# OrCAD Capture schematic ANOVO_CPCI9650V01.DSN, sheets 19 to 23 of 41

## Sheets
19 -GIGA LAN1: size C; title: 19--GIGA LAN1
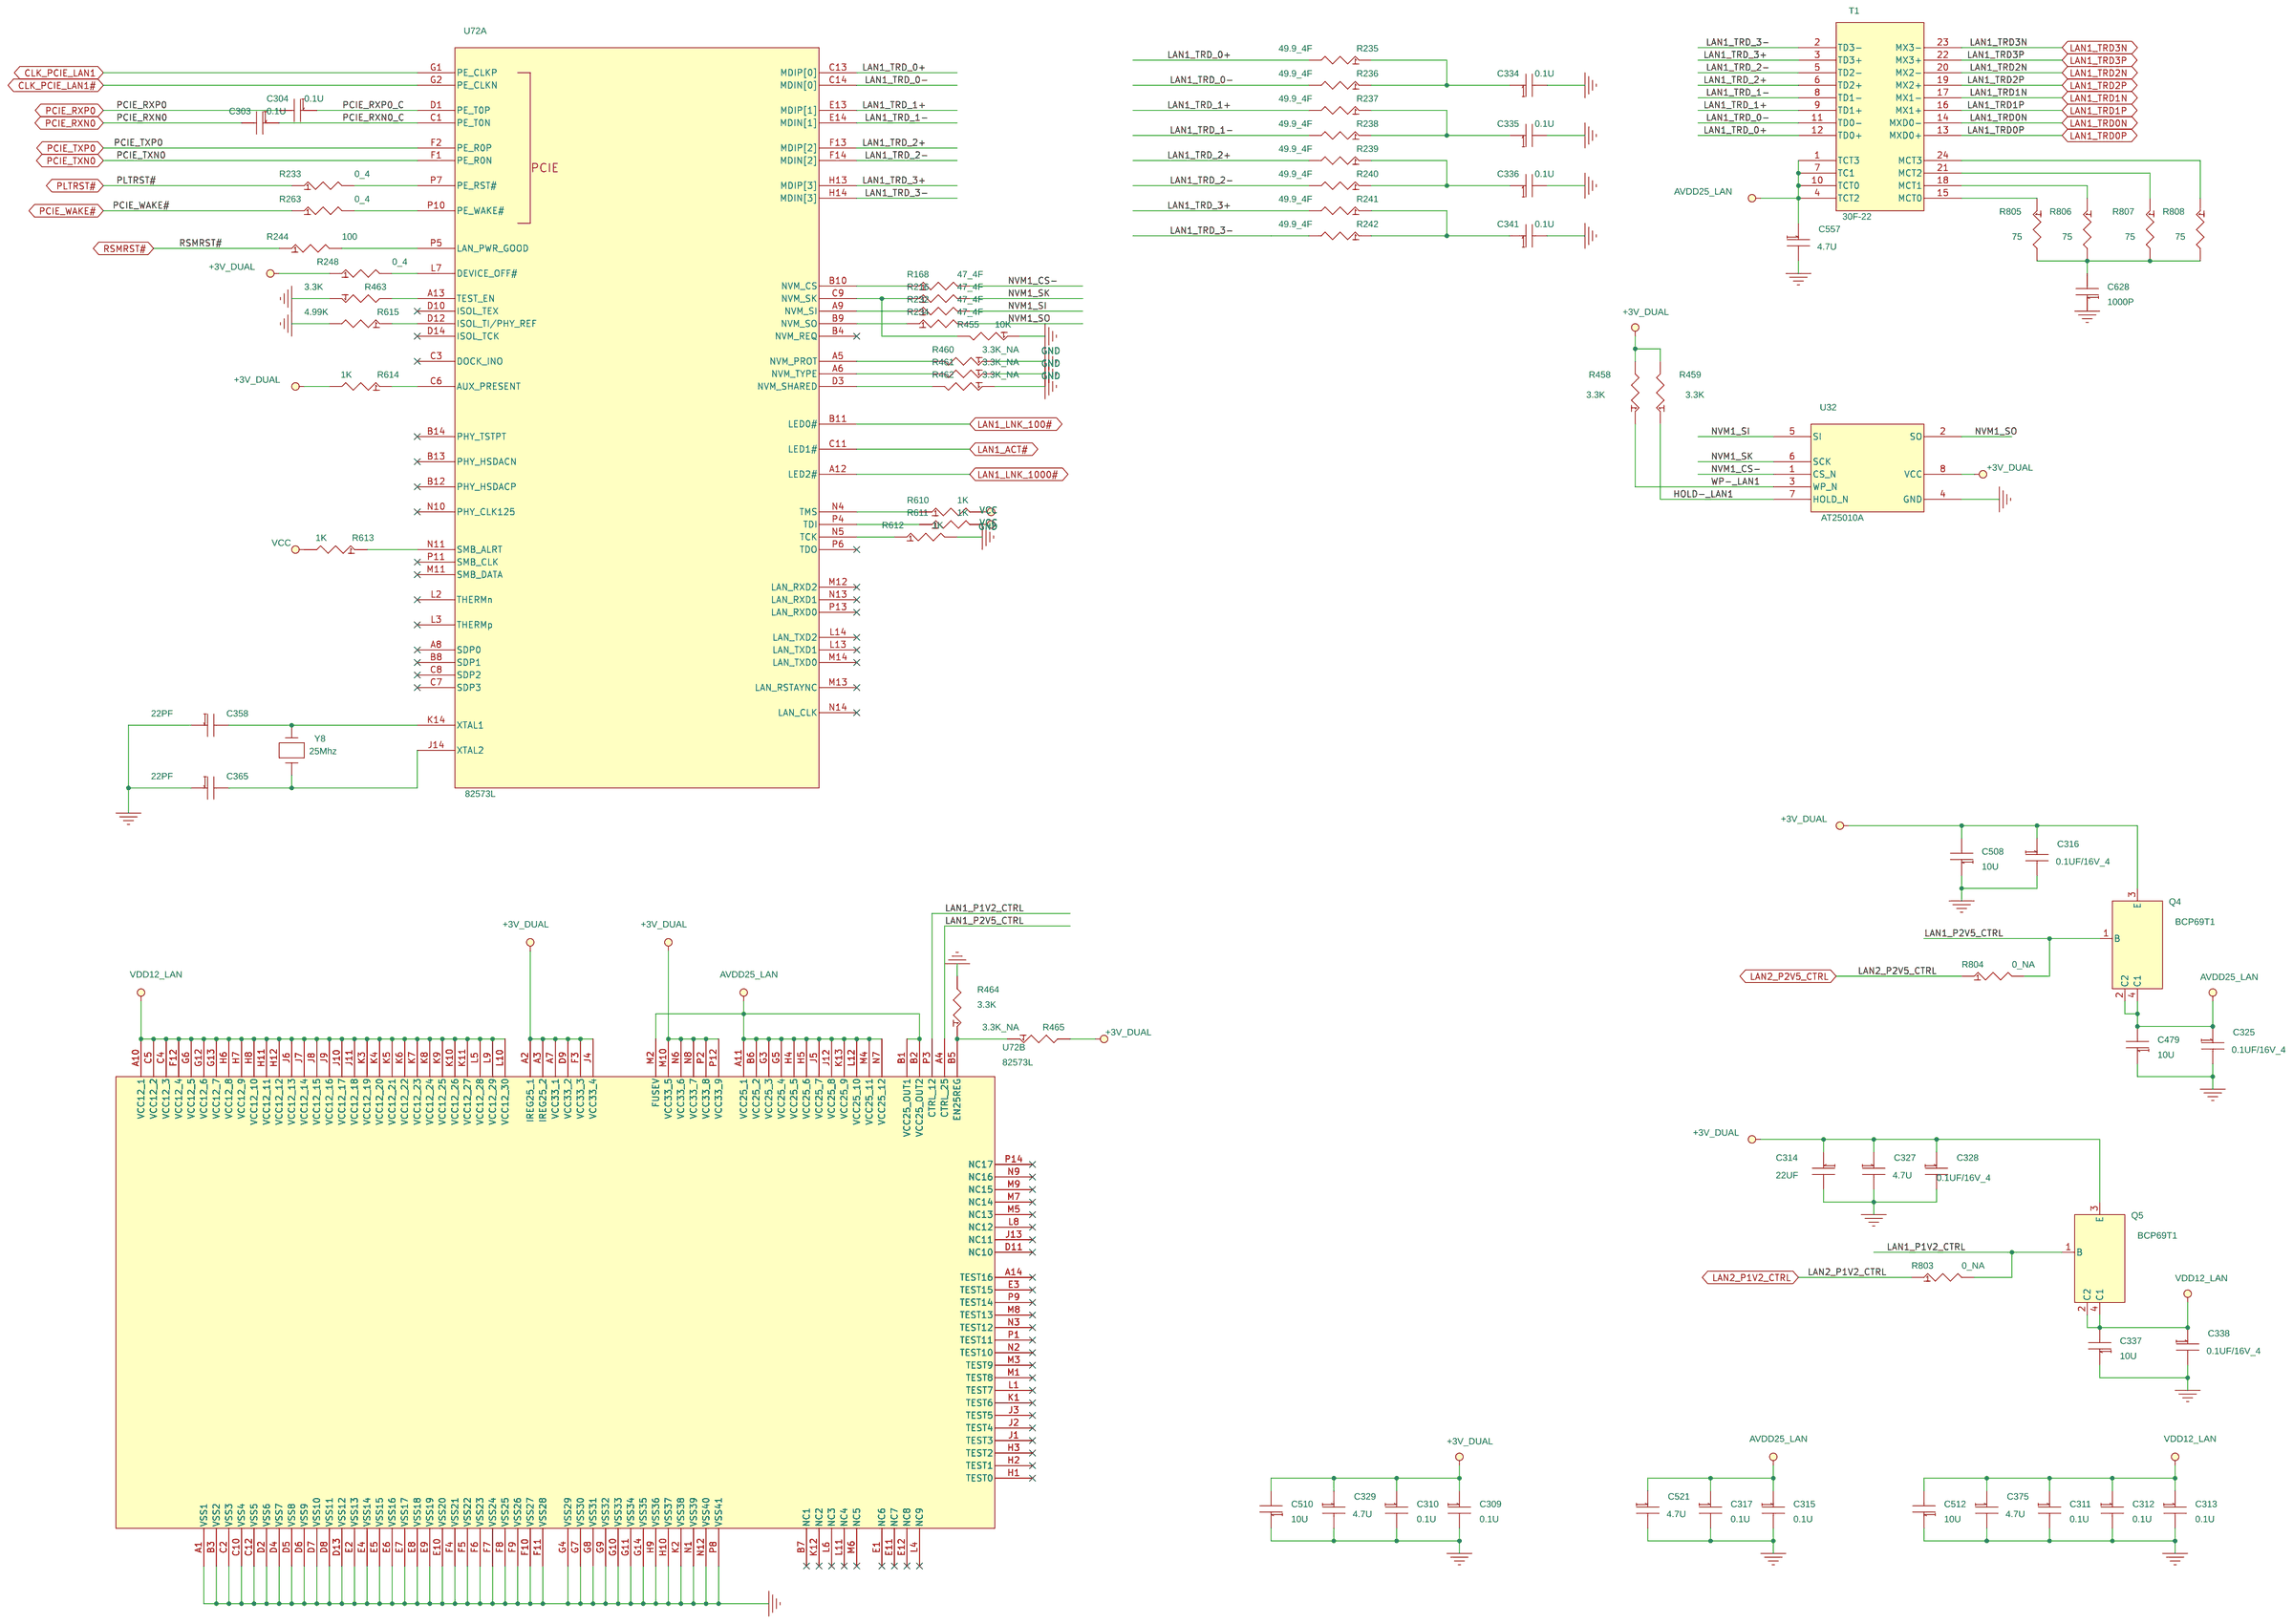
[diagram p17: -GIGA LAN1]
20 -GIGA LAN2: size C; title: 20--GIGA LAN2
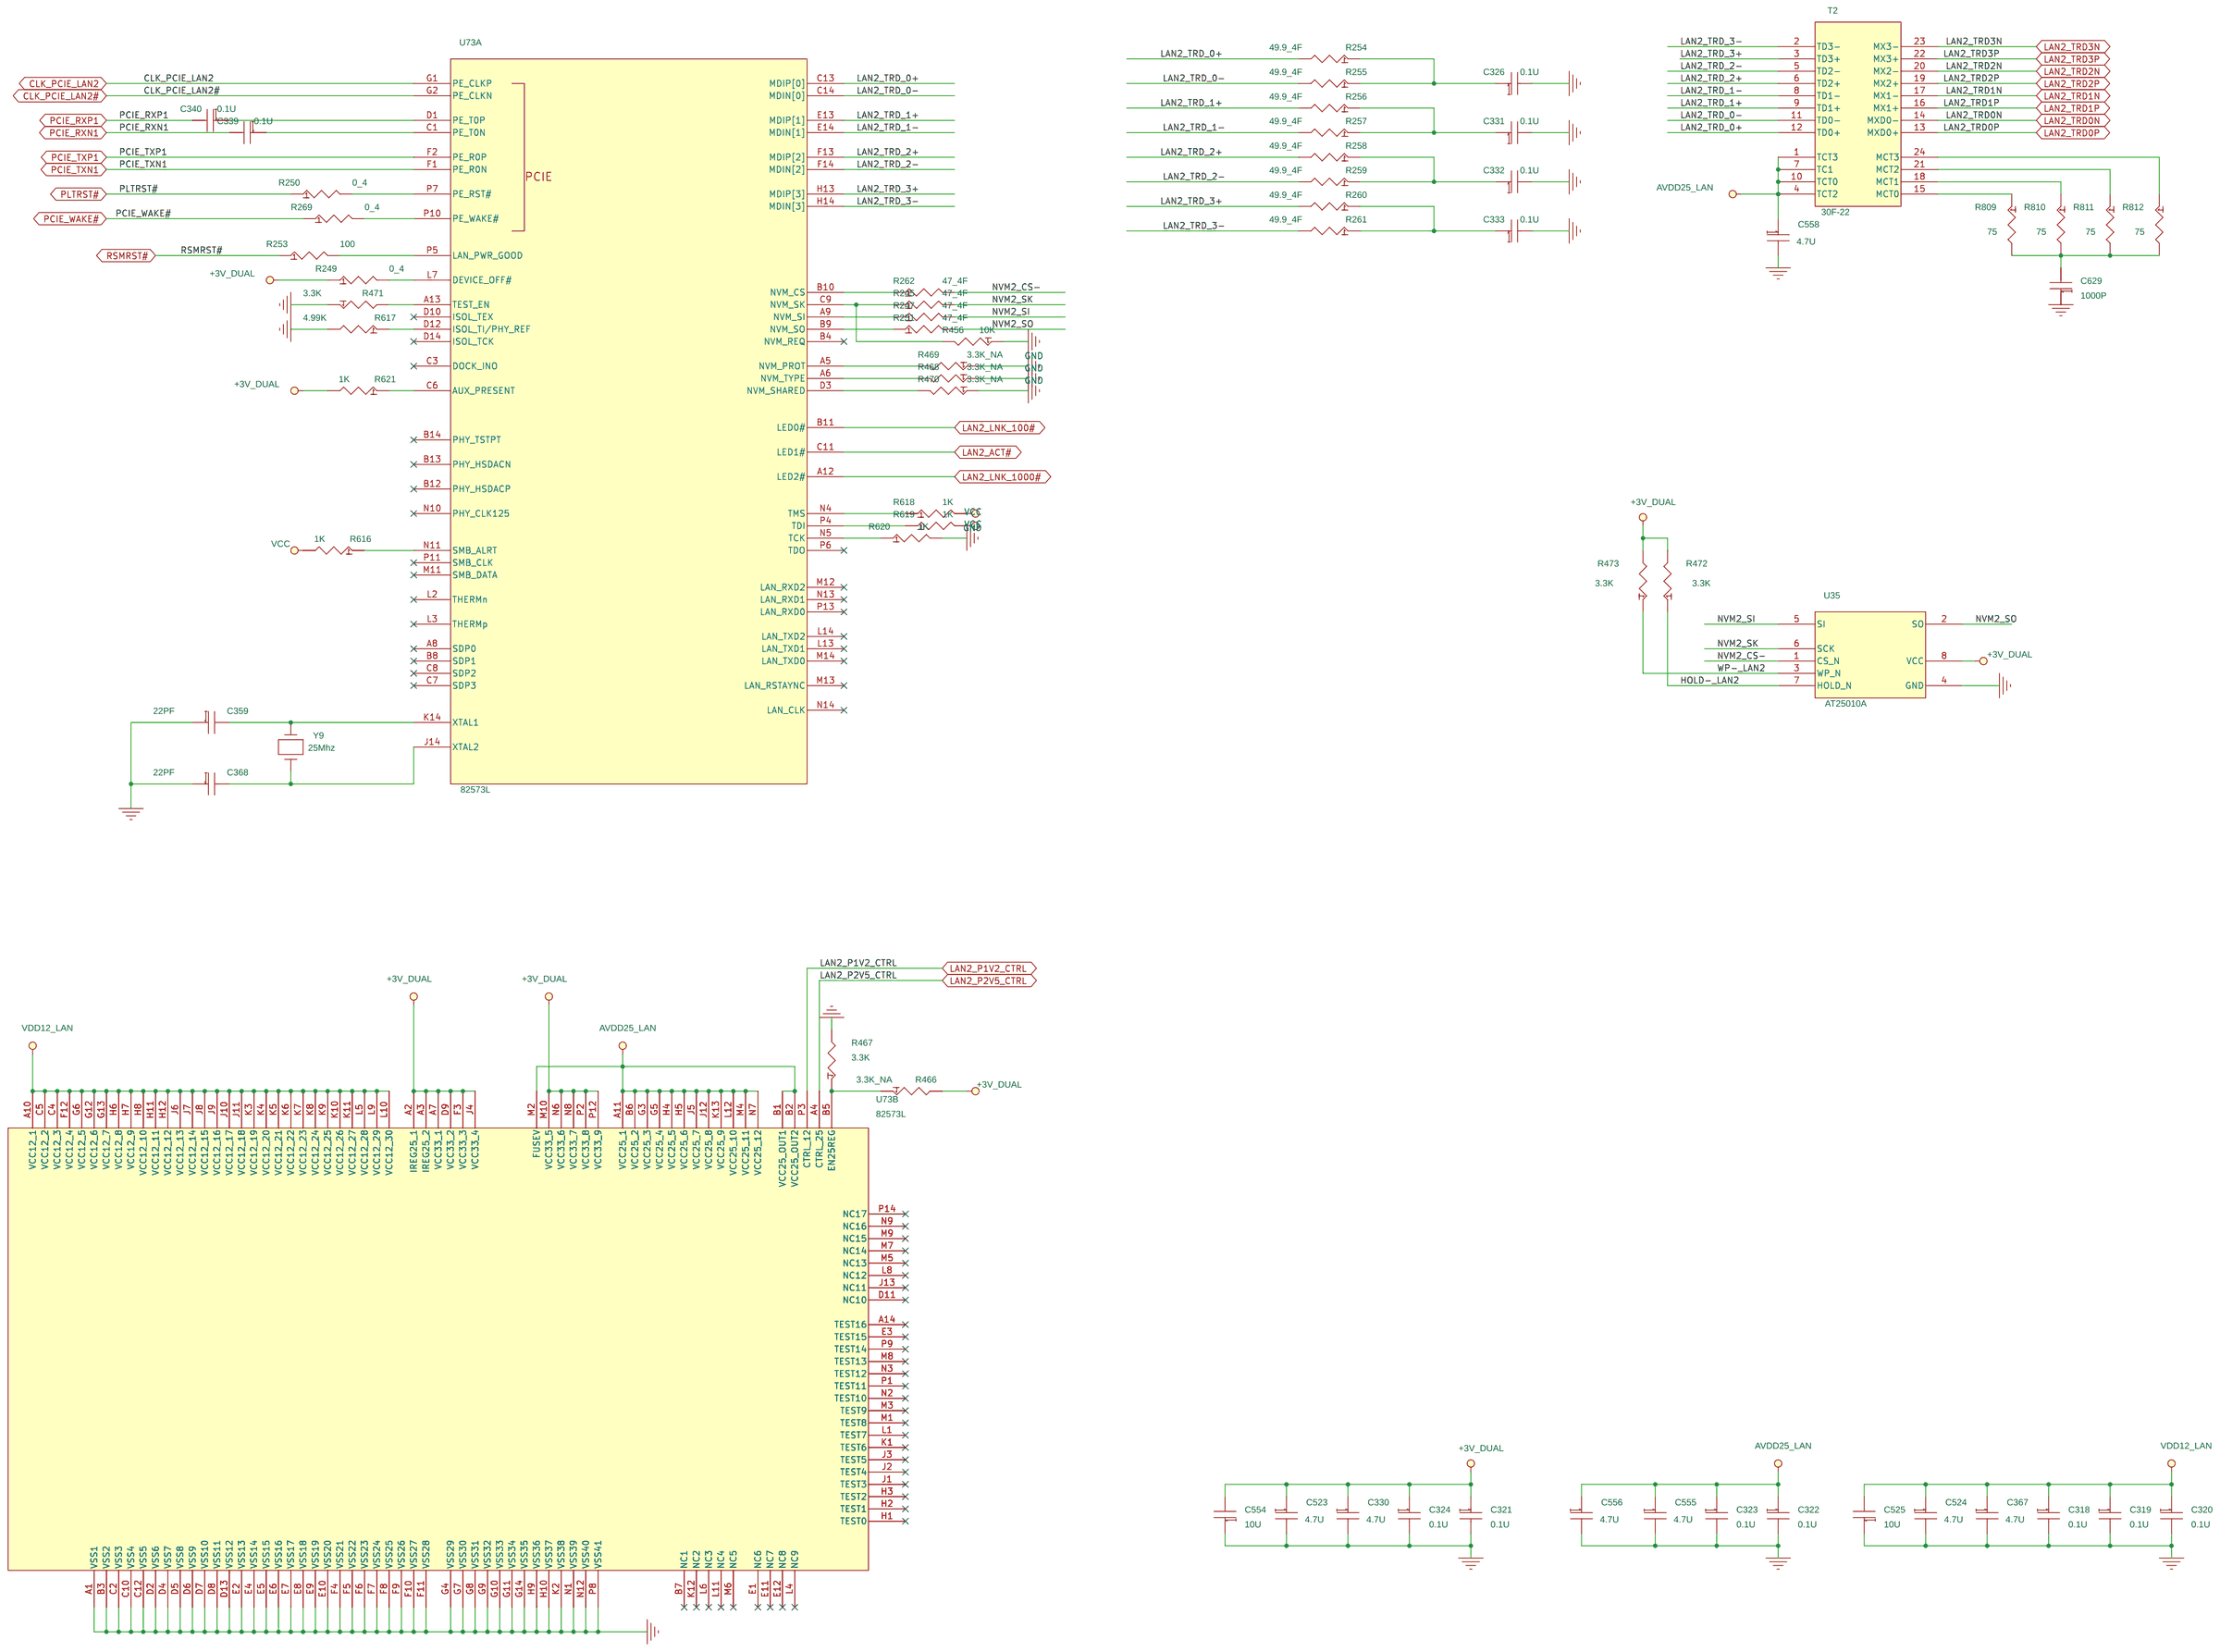
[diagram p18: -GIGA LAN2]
21 -SIO ITE8781F 4 COM PORTS: size C; title: 21--82559 PCI LAN
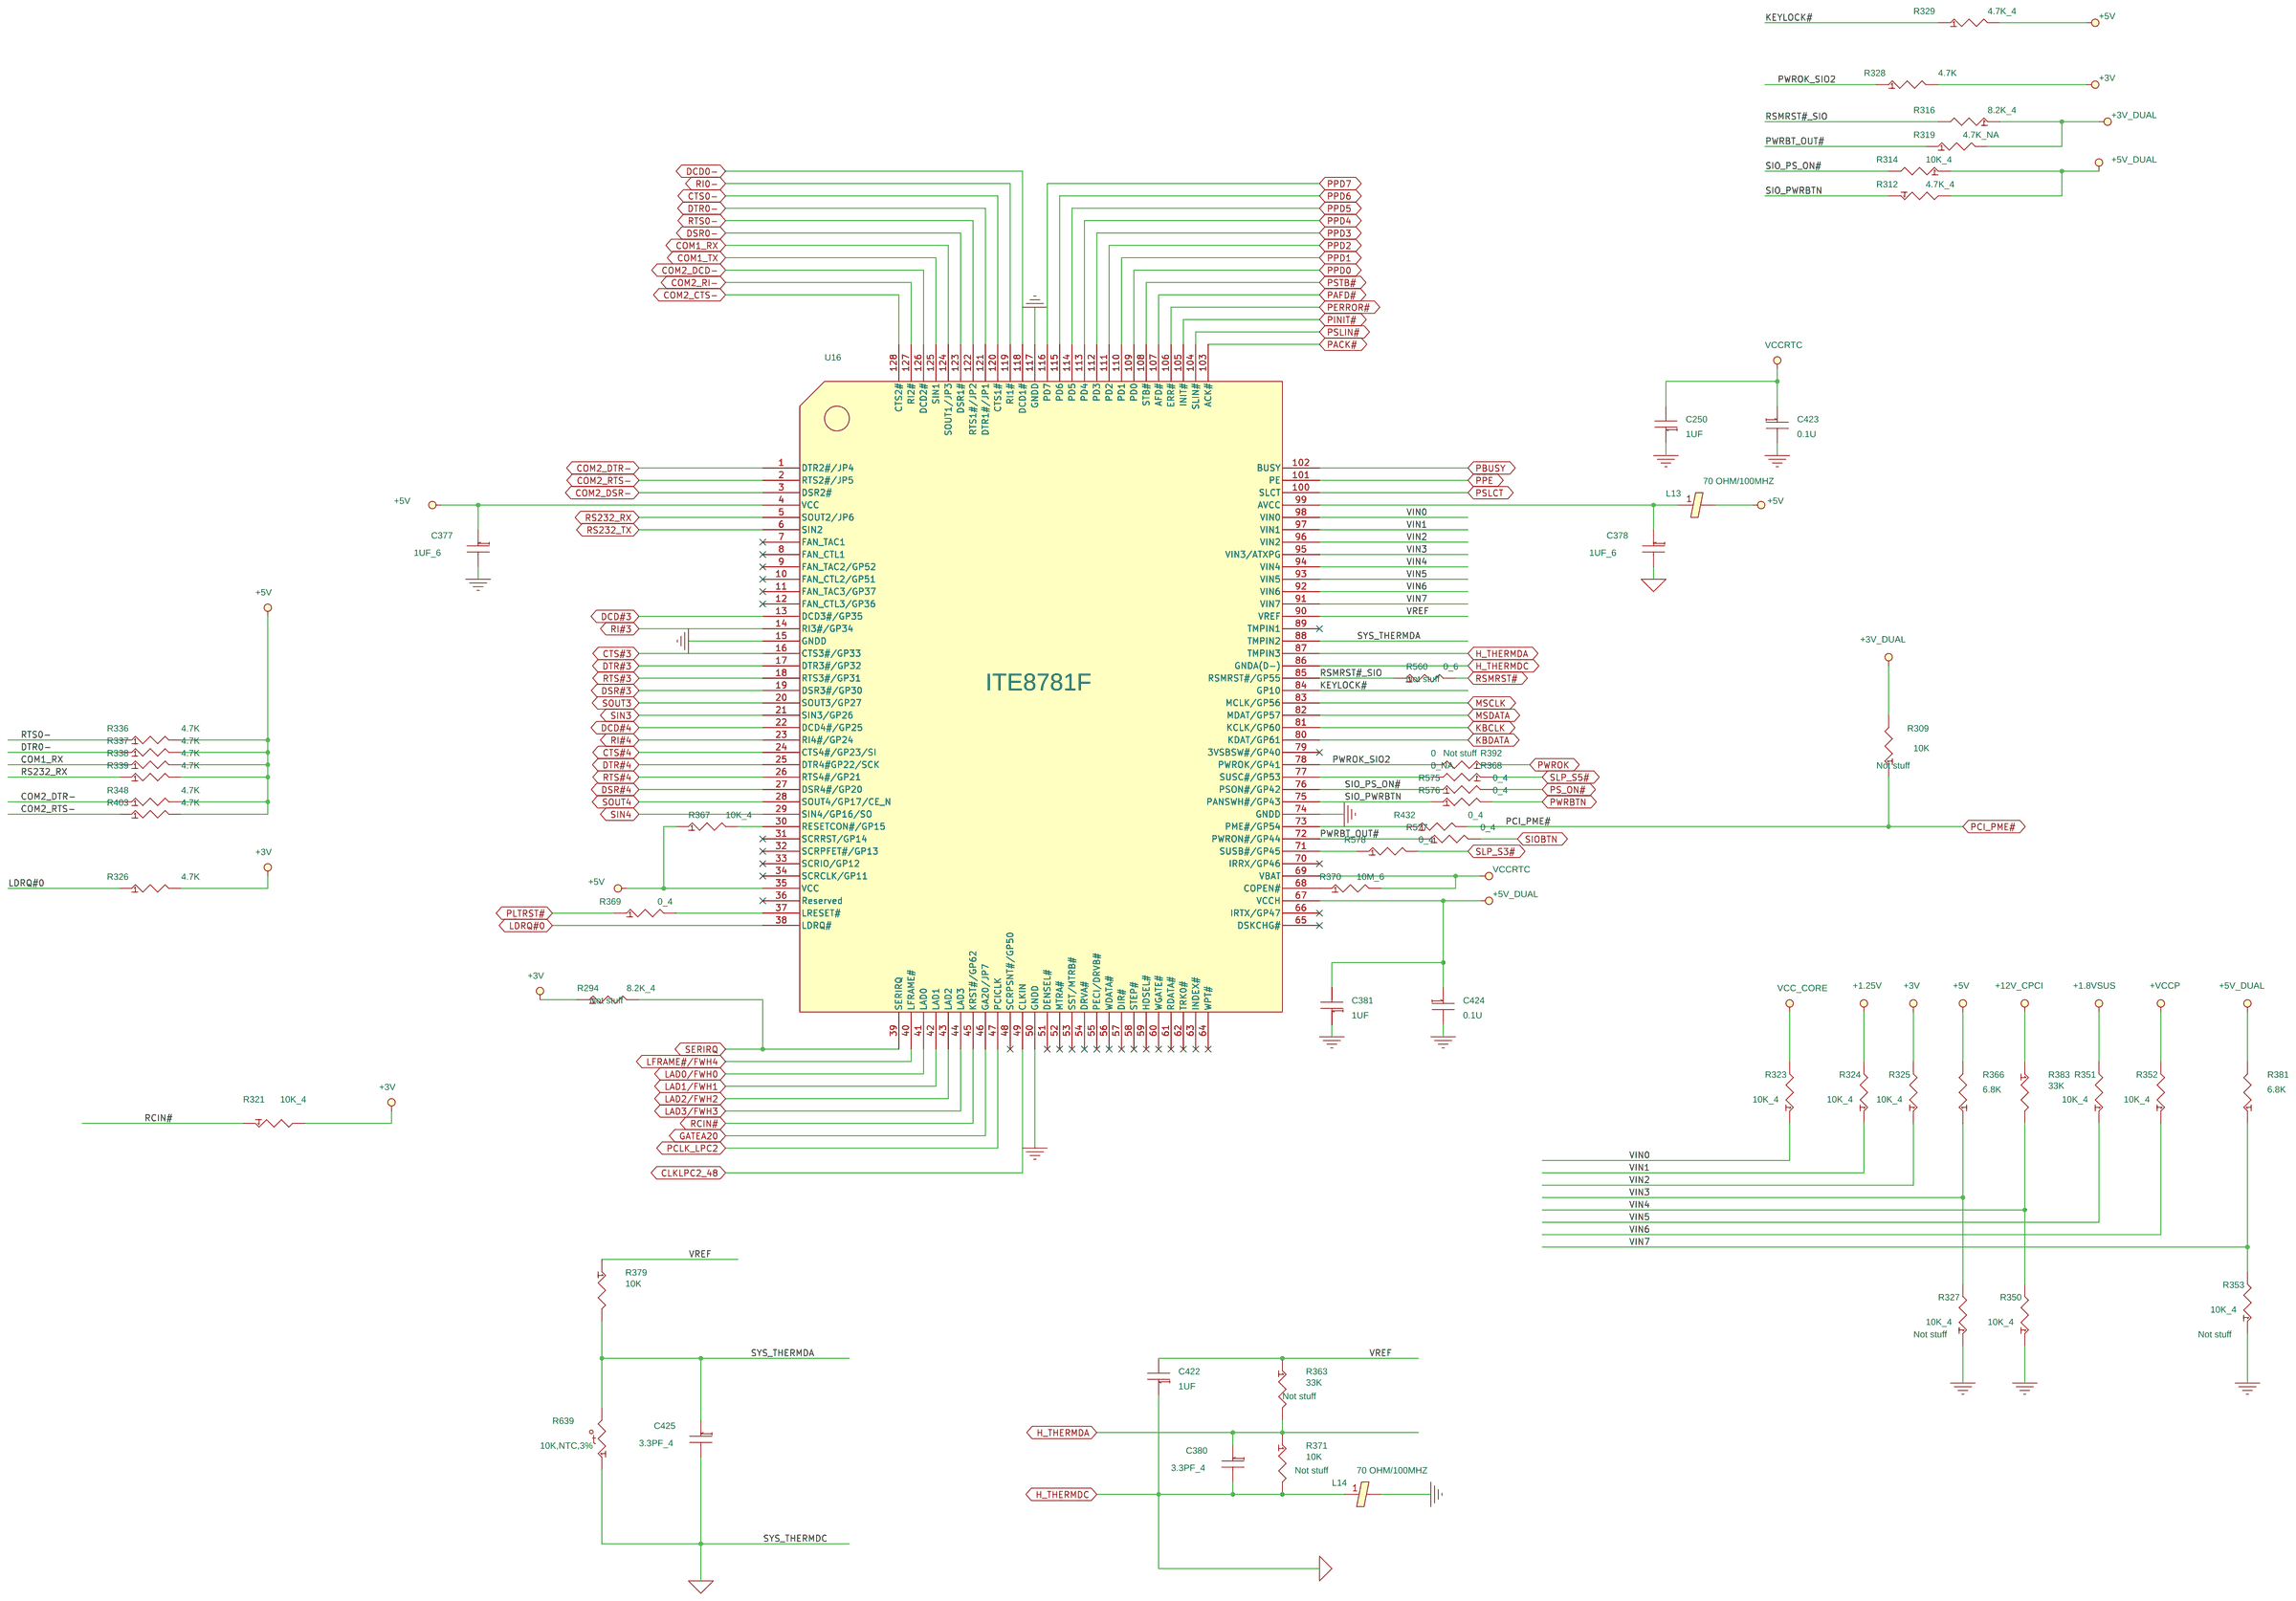
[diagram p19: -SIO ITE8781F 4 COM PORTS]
22 -COM 3 4 RS232: size C; title: 22--NC
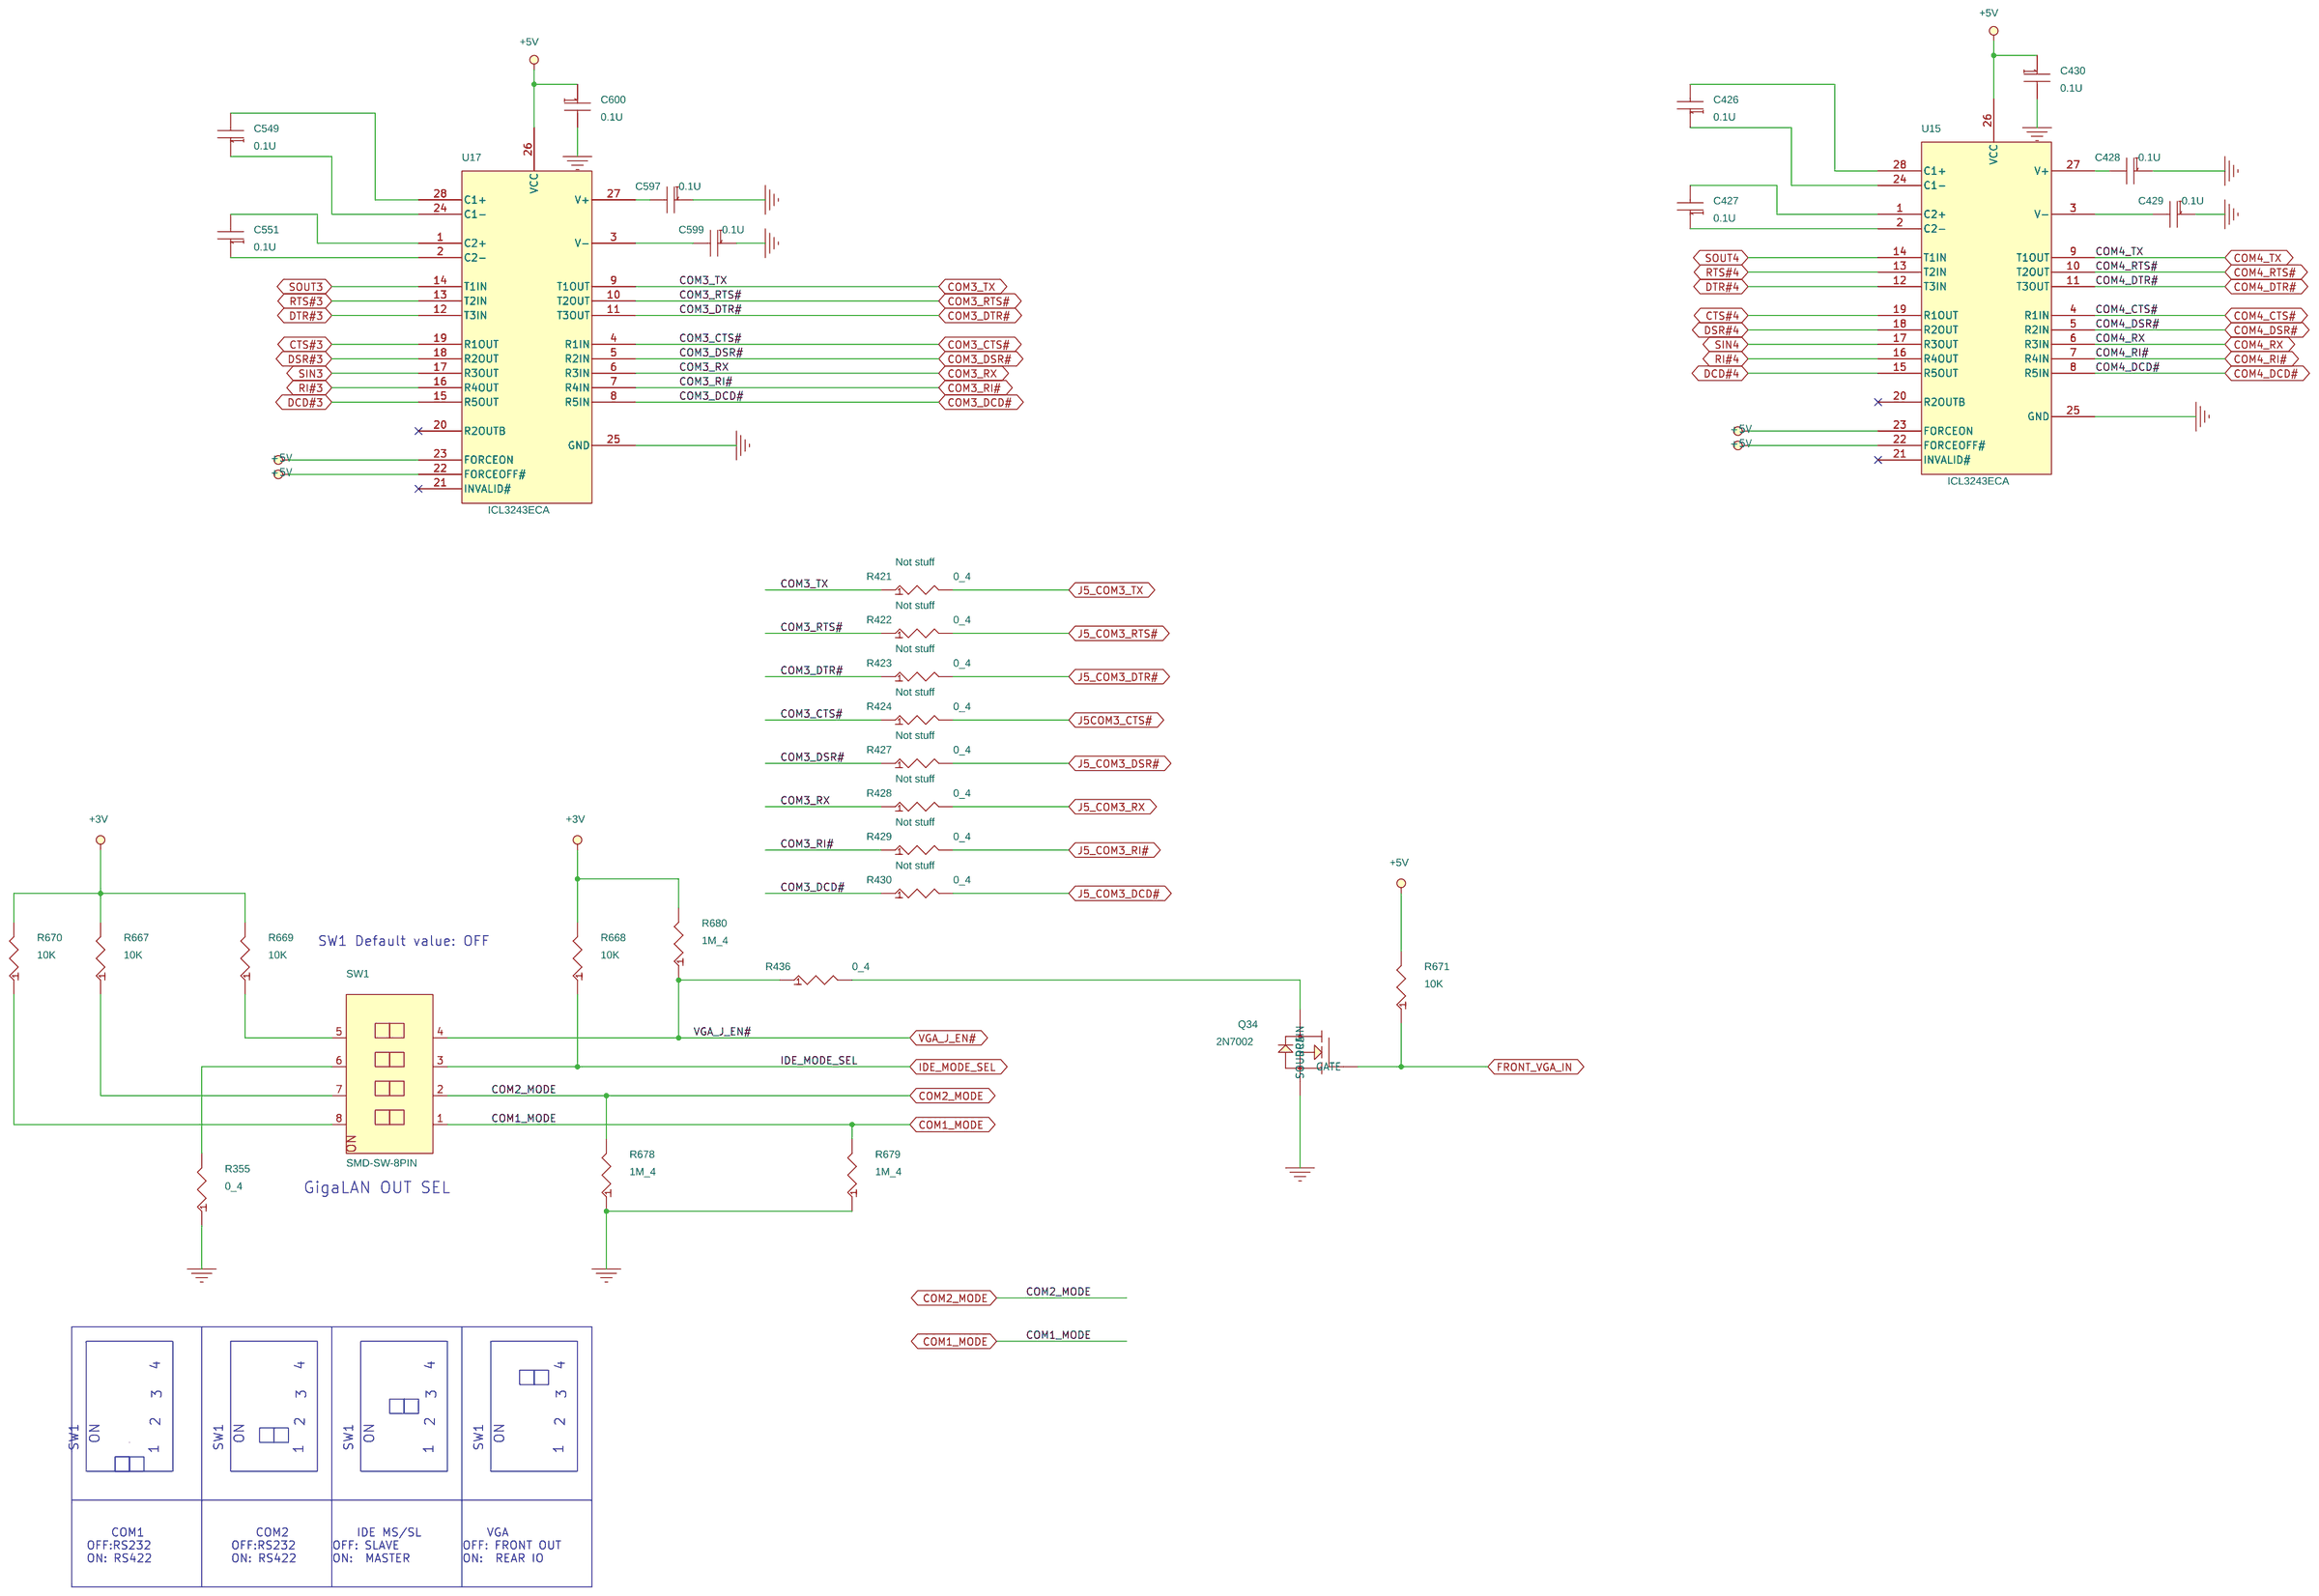
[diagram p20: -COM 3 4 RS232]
23 -CODAC ALC888: size C; title: 23--CODAC ALC888
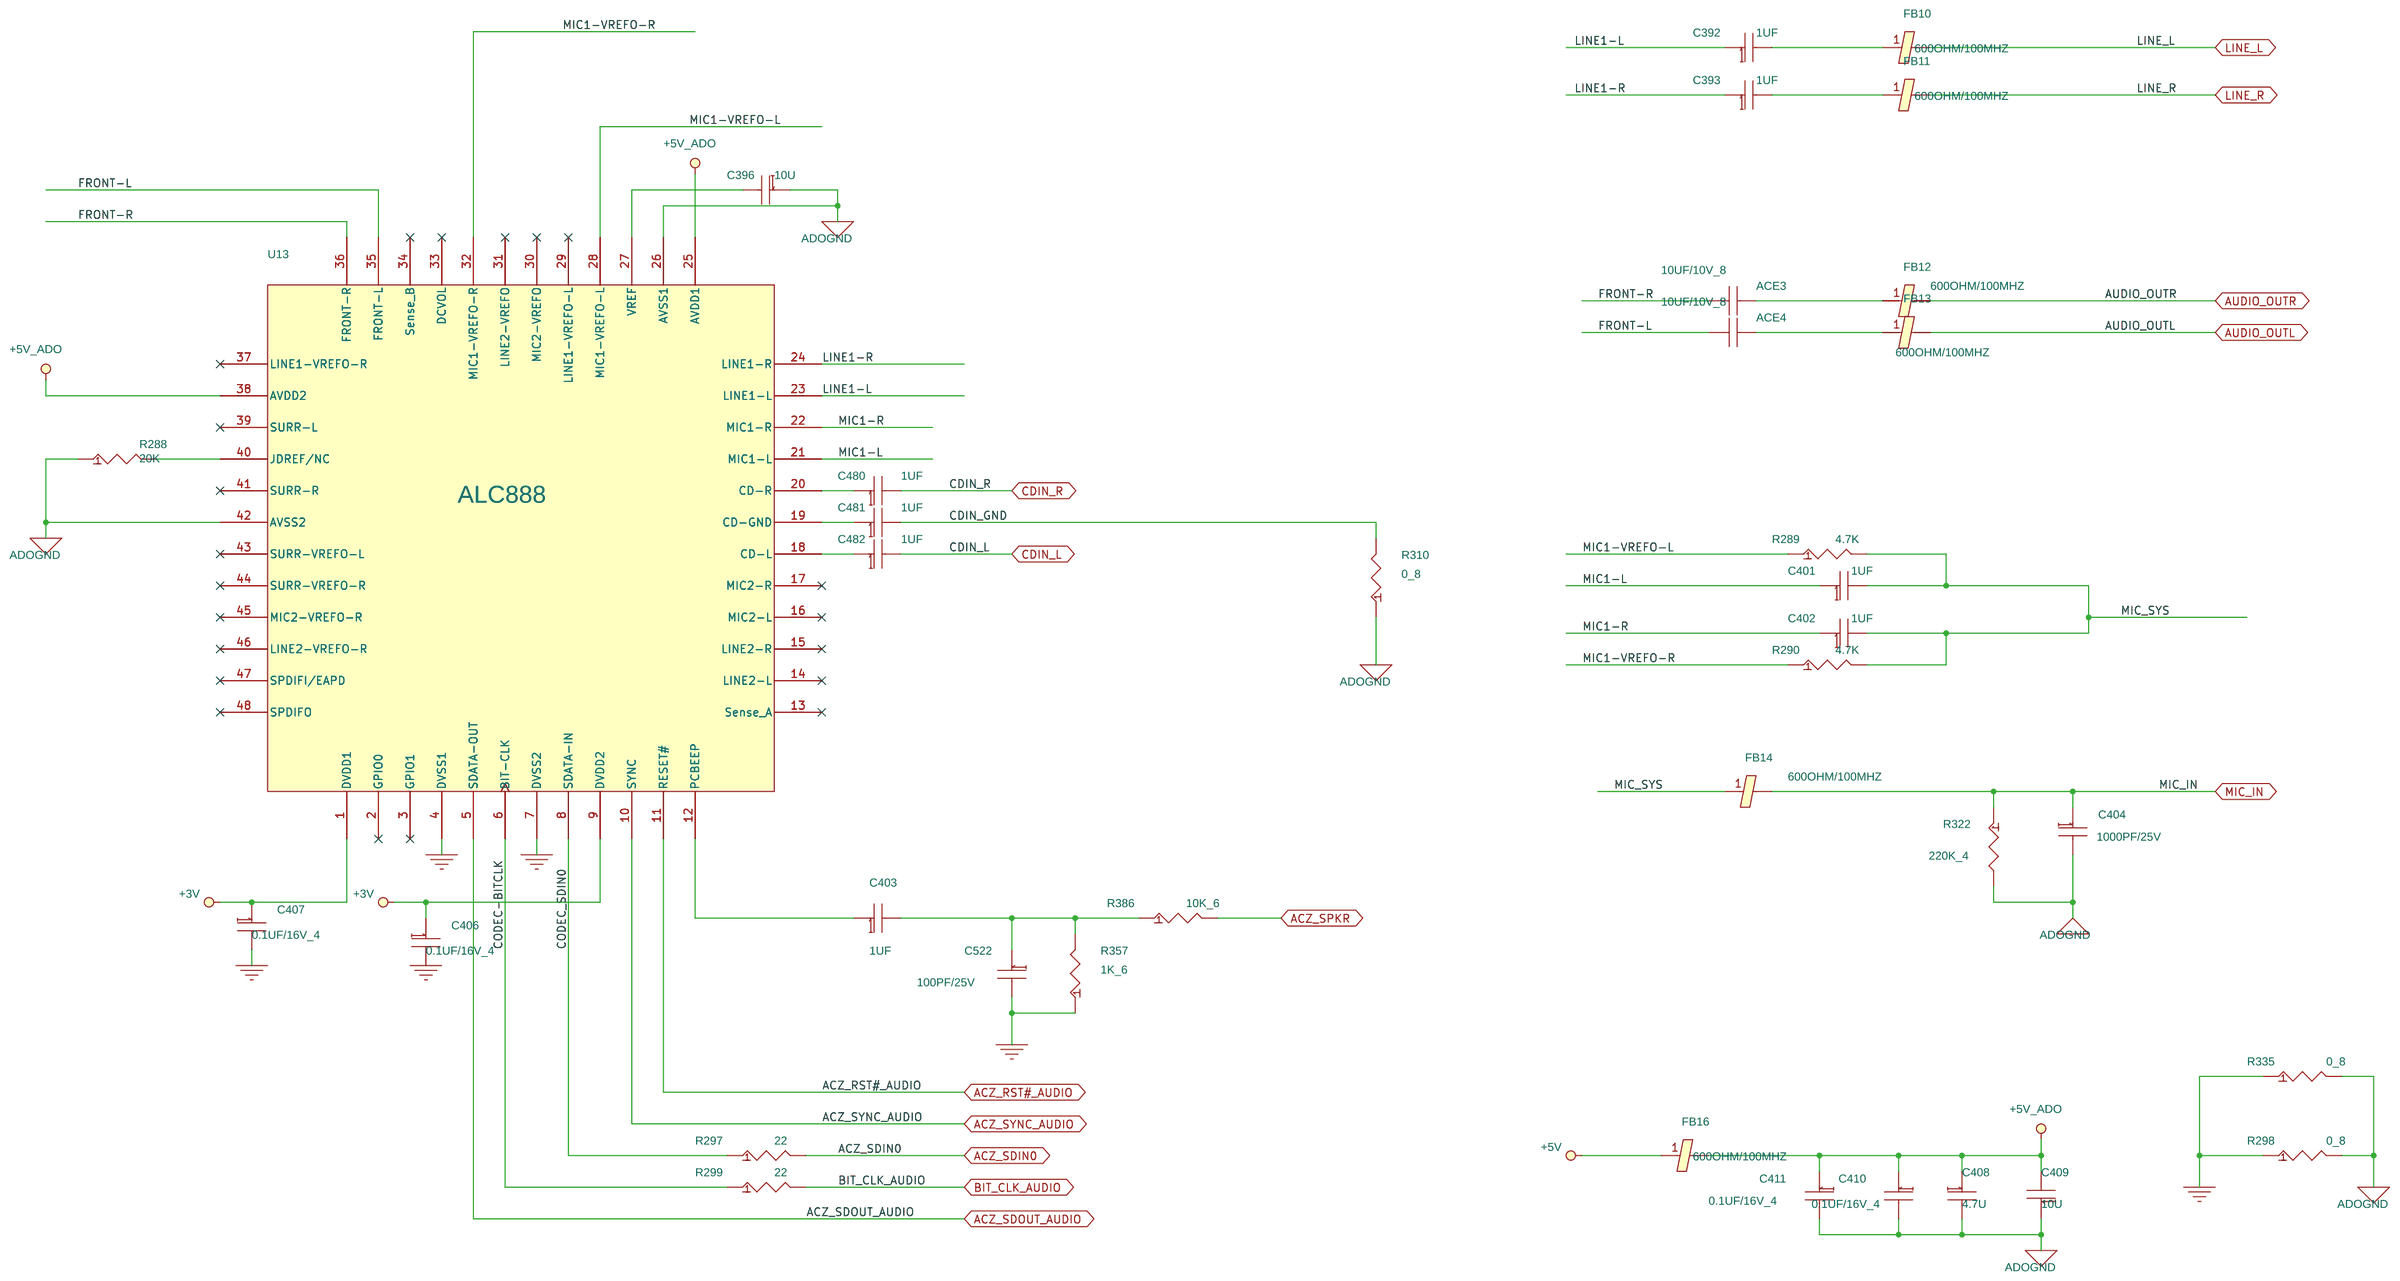
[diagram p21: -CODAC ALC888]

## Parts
sheet -CODAC ALC888
ACE3  10UF/10V_8  [0805D]
ACE4  10UF/10V_8  [0805D]
C392  1UF  [0402D]
C393  1UF  [0402D]
C396  10U  [0805D]
C401  1UF  [0402D]
C402  1UF  [0402D]
C403  1UF  [0402D]
C404  1000PF/25V  [0402D]
C406  0.1UF/16V_4  [0402D]
C407  0.1UF/16V_4  [0402D]
C408  4.7U  [0805D]
C409  10U  [0805D]
C410  0.1UF/16V_4  [0402D]
C411  0.1UF/16V_4  [0402D]
C480  1UF  [0402D]
C481  1UF  [0402D]
C482  1UF  [0402D]
C522  100PF/25V  [0603D]
FB10  600OHM/100MHZ  [0603D]
FB11  600OHM/100MHZ  [0603D]
FB12  600OHM/100MHZ  [0603D]
FB13  600OHM/100MHZ  [0603D]
FB14  600OHM/100MHZ  [0603D]
FB16  600OHM/100MHZ  [0603D]
R288  20K  [0402D]
R289  4.7K  [0402D]
R290  4.7K  [0402D]
R297  22  [0402D]
R298  0_8  [0805D]
R299  22  [0402D]
R310  0_8  [0805D]
R322  220K_4  [0402D]
R335  0_8  [0805D]
R357  1K_6  [0603D]
R386  10K_6  [0603D]
U13  ALC888  [LQFP48-9X9-5]
sheet -COM 3 4 RS232
C426  0.1U  [0402D]
C427  0.1U  [0402D]
C428  0.1U  [0402D]
C429  0.1U  [0402D]
C430  0.1U  [0402D]
C549  0.1U  [0402D]
C551  0.1U  [0402D]
C597  0.1U  [0402D]
C599  0.1U  [0402D]
C600  0.1U  [0402D]
Q34  2N7002  [SOT23N_5]
R355  0_4  [0402D]
R421  0_4  [0402D]
R422  0_4  [0402D]
R423  0_4  [0402D]
R424  0_4  [0402D]
R427  0_4  [0402D]
R428  0_4  [0402D]
R429  0_4  [0402D]
R430  0_4  [0402D]
R436  0_4  [0402D]
R667  10K  [0402D]
R668  10K  [0402D]
R669  10K  [0402D]
R670  10K  [0402D]
R671  10K  [0402D]
R678  1M_4  [0402D]
R679  1M_4  [0402D]
R680  1M_4  [0402D]
SW1  SMD-SW-8PIN  [SW-4X2SS]
U15  ICL3243ECA  [SSOP28A]
U17  ICL3243ECA  [SSOP28A]
sheet -GIGA LAN1
C303  0.1U  [0402D]
C304  0.1U  [0402D]
C309  0.1U  [0402D]
C310  0.1U  [0402D]
C311  0.1U  [0402D]
C312  0.1U  [0402D]
C313  0.1U  [0402D]
C314  22UF  [0805D]
C315  0.1U  [0402D]
C316  0.1UF/16V_4  [0402D]
C317  0.1U  [0402D]
C325  0.1UF/16V_4  [0402D]
C327  4.7U  [0805D]
C328  0.1UF/16V_4  [0402D]
C329  4.7U  [0805D]
C334  0.1U  [0402D]
C335  0.1U  [0402D]
C336  0.1U  [0402D]
C337  10U  [0805D]
C338  0.1UF/16V_4  [0402D]
C341  0.1U  [0402D]
C358  22PF  [0402D]
C365  22PF  [0402D]
C375  4.7U  [0805D]
C479  10U  [0805D]
C508  10U  [0805D]
C510  10U  [0805D]
C512  10U  [0805D]
C521  4.7U  [0805D]
C557  4.7U  [0805D]
C628  1000P  [1206A]
Q4  BCP69T1  [SOT223]
Q5  BCP69T1  [SOT223]
R168  47_4F  [0402D]
R216  47_4F  [0402D]
R232  47_4F  [0402D]
R233  0_4  [0402D]
R234  47_4F  [0402D]
R235  49.9_4F  [0402D]
R236  49.9_4F  [0402D]
R237  49.9_4F  [0402D]
R238  49.9_4F  [0402D]
R239  49.9_4F  [0402D]
R240  49.9_4F  [0402D]
R241  49.9_4F  [0402D]
R242  49.9_4F  [0402D]
R244  100  [0402D]
R248  0_4  [0402D]
R263  0_4  [0402D]
R455  10K  [0402D]
R458  3.3K  [0402D]
R459  3.3K  [0402D]
R460  3.3K_NA  [0402D]
R461  3.3K_NA  [0402D]
R462  3.3K_NA  [0402D]
R463  3.3K  [0402D]
R464  3.3K  [0402D]
R465  3.3K_NA  [0402D]
R610  1K  [0402D]
R611  1K  [0402D]
R612  1K  [0402D]
R613  1K  [0402D]
R614  1K  [0402D]
R615  4.99K  [0402D]
R803  0_NA  [0402D]
R804  0_NA  [0402D]
R805  75  [0402D]
R806  75  [0402D]
R807  75  [0402D]
R808  75  [0402D]
T1  30F-22  [XFMR_H500X]
U32  AT25010A  [SO8]
U72  82573L  [MBGA196]  (sections A,B)
Y8  25Mhz  [FA-365]
sheet -GIGA LAN2
C318  0.1U  [0402D]
C319  0.1U  [0402D]
C320  0.1U  [0402D]
C321  0.1U  [0402D]
C322  0.1U  [0402D]
C323  0.1U  [0402D]
C324  0.1U  [0402D]
C326  0.1U  [0402D]
C330  4.7U  [0805D]
C331  0.1U  [0402D]
C332  0.1U  [0402D]
C333  0.1U  [0402D]
C339  0.1U  [0402D]
C340  0.1U  [0402D]
C359  22PF  [0402D]
C367  4.7U  [0805D]
C368  22PF  [0402D]
C523  4.7U  [0805D]
C524  4.7U  [0805D]
C525  10U  [0805D]
C554  10U  [0805D]
C555  4.7U  [0805D]
C556  4.7U  [0805D]
C558  4.7U  [0805D]
C629  1000P  [1206A]
R245  47_4F  [0402D]
R247  47_4F  [0402D]
R249  0_4  [0402D]
R250  0_4  [0402D]
R251  47_4F  [0402D]
R253  100  [0402D]
R254  49.9_4F  [0402D]
R255  49.9_4F  [0402D]
R256  49.9_4F  [0402D]
R257  49.9_4F  [0402D]
R258  49.9_4F  [0402D]
R259  49.9_4F  [0402D]
R260  49.9_4F  [0402D]
R261  49.9_4F  [0402D]
R262  47_4F  [0402D]
R269  0_4  [0402D]
R456  10K  [0402D]
R466  3.3K_NA  [0402D]
R467  3.3K  [0402D]
R468  3.3K_NA  [0402D]
R469  3.3K_NA  [0402D]
R470  3.3K_NA  [0402D]
R471  3.3K  [0402D]
R472  3.3K  [0402D]
R473  3.3K  [0402D]
R616  1K  [0402D]
R617  4.99K  [0402D]
R618  1K  [0402D]
R619  1K  [0402D]
R620  1K  [0402D]
R621  1K  [0402D]
R809  75  [0402D]
R810  75  [0402D]
R811  75  [0402D]
R812  75  [0402D]
T2  30F-22  [XFMR_H500X]
U35  AT25010A  [SO8]
U73  82573L  [MBGA196]  (sections A,B)
Y9  25Mhz  [FA-365]
sheet -SIO ITE8781F 4 COM PORTS
C250  1UF  [0402D]
C377  1UF_6  [0603D]
C378  1UF_6  [0603D]
C380  3.3PF_4  [0402D]
C381  1UF  [0402D]
C422  1UF  [0402D]
C423  0.1U  [0402D]
C424  0.1U  [0402D]
C425  3.3PF_4  [0402D]
L13  70 OHM/100MHZ  [0805D]
L14  70 OHM/100MHZ  [0805D]
R294  8.2K_4  [0402D]
R309  10K  [0402D]
R312  4.7K_4  [0402D]
R314  10K_4  [0402D]
R316  8.2K_4  [0402D]
R319  4.7K_NA  [0402D]
R321  10K_4  [0402D]
R323  10K_4  [0402D]
R324  10K_4  [0402D]
R325  10K_4  [0402D]
R326  4.7K  [0402D]
R327  10K_4  [0402D]
R328  4.7K  [0402D]
R329  4.7K_4  [0402D]
R336  4.7K  [0402D]
R337  4.7K  [0402D]
R338  4.7K  [0402D]
R339  4.7K  [0402D]
R348  4.7K  [0402D]
R350  10K_4  [0402D]
R351  10K_4  [0402D]
R352  10K_4  [0402D]
R353  10K_4  [0402D]
R363  33K  [0402D]
R366  6.8K  [0603D]
R367  10K_4  [0402D]
R368  0_NA  [0402D]
R369  0_4  [0402D]
R370  10M_6  [0603D]
R371  10K  [0402D]
R379  10K  [0402D]
R381  6.8K  [0603D]
R383  33K  [0402D]
R392  0  [0402D]
R403  4.7K  [0402D]
R432  0_4  [0402D]
R560  0_6  [0603D]
R575  0_4  [0402D]
R576  0_4  [0402D]
R577  0_4  [0402D]
R578  0_4  [0402D]
R639  10K,NTC,3%  [0603D]
U16  ITE8781F  [I121280H]

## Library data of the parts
ACE3 ACE4 = C: ANOVO DESCRIPTION: CAP;10U,10V,+80-20%,0805,Y5V,SMT; ANOVO PART NUMBER: 272002106401
C250 C381 C392 C393 C401-C403 C422 C480-C482 = CAP_NP: ANOVO DESCRIPTION: CAP, 1UF, 6.3V ,10%, 0402, X7R ,SMT; ANOVO PART NUMBER: 272041105200; Part Type: CCAP
C337 C396 C409 C479 C508 C510 C512 C525 C554 = CAP_NP: ANOVO DESCRIPTION: CAP;10U,10V,+80-20%,0805,Y5V,SMT; ANOVO PART NUMBER: 272002106401; Part Type: CCAP
C404 = CAP_NP: ANOVO DESCRIPTION: CAP;1000P ,16V ,10% ,0402 ,X7R ,SMT; ANOVO PART NUMBER: 272043102201; Part Type: CCAP
C316 C325 C328 C338 C406 C407 C410 C411 = CAP_NP: ANOVO DESCRIPTION: CAP;0.1U ,16V ,+80-20% ,0402 ,Y5V ,SMT; ANOVO PART NUMBER: 272043104401; BACKSIDE: 0; Part Type: CCAP; SMT: YES
C327 C329 C330 C367 C375 C408 C521 C523 C524 C555-C558 = CAP_NP: ANOVO DESCRIPTION: CAP;4.7U ,10V ,+80-20% ,0805 ,Y5V ,SMT; ANOVO PART NUMBER: 272002475401; Part Type: CCAP
C522 = CAP_NP: ANOVO DESCRIPTION: CAP;100P ,50V ,5% ,0603 ,NPO ,SMT; ANOVO PART NUMBER: 272075101101; BACKSIDE: 0; Part Type: CCAP; SMT: YES
FB10-FB14 FB16 = FERRITE_BEAD: ANOVO DESCRIPTION: FERRITE CHIP;600 OHM/100MHZ,0603,350mA,SMT; ANOVO PART NUMBER: 273006012200; Part Type: FERRITE BEAD
R288 = R_v2: ANOVO DESCRIPTION: RES;20K ,1/16W ,1% ,0402 ,SMT; ANOVO PART NUMBER: 271040203101; BACKSIDE: 0; Part Type: RESISTOR; SMT: YES
R289 R290 R326 R328 R336-R339 R348 R403 = R_v2: ANOVO DESCRIPTION: RES;4.7K ,1/16W ,5% ,0402 ,SMT; ANOVO PART NUMBER: 271040472301; Part Type: RESISTOR
R297 R299 = R_v2: ANOVO DESCRIPTION: RES;22 ,1/16W ,5% ,0402 ,SMT; ANOVO PART NUMBER: 271040220301; POWER: 1/16W; Part Type: RESISTOR
R298 R310 R335 = R_v2: ANOVO DESCRIPTION: RES,0 ,1/8W ,5% ,0805 ,SMT; ANOVO PART NUMBER: 271002000301
R322 = R_v2: 8ND PART FIELD: BOT; ANOVO DESCRIPTION: RES;220K ,1/16W ,5% ,0402 ,SMT; ANOVO PART NUMBER: 271040224301; BACKSIDE: 0; Function Code: ADO; Part Type: RESISTOR; ROOM: AUDIO; SMT: YES; Stock: OK
R357 = R_v2: ANOVO DESCRIPTION: RES;1K ,1/10W ,1% ,0603 ,SMT; ANOVO PART NUMBER: 271071102101; POWER: 1/16W; Part Type: RESISTOR
R386 = R_v2: ANOVO DESCRIPTION: RES;10K ,1/10W ,1% ,0603 ,SMT; ANOVO PART NUMBER: 271071103101; POWER: 1/16W; Part Type: RESISTOR
U13 = ALC880-M-LQFP48_0_v2: 8ND PART FIELD: TOP; ANOVO DESCRIPTION: IC;ALC888,Audio Codec,LQFP,48P,Reltek; ANOVO PART NUMBER: 286308880001; Function Code: ADO
C303 C304 C309-C313 C315 C317-C324 C326 C331-C336 C339-C341 C423 C424 C426-C430 C549 C551 C597 C599 C600 = CAP_NP: ANOVO DESCRIPTION: CAP;0.1U ,16V ,10% ,0402 ,X7R ,SMT; ANOVO PART NUMBER: 272043104201; Part Type: CCAP
Q34 = MOSFET_N_3P: ANOVO DESCRIPTION: TRANS;2N7002,N-MOSFET,60V,500mA,SOT23; ANOVO PART NUMBER: 288227002001; BACKSIDE: 0; Part Type: MOSFET; SMT: YES
R355 R432 R436 R575-R578 = R_v2: ANOVO DESCRIPTION: RES;0 ,1/16W ,5% ,0402 ,SMT; ANOVO PART NUMBER: 271040000301; Part Type: RESISTOR; SMT: YES
R421-R424 R427-R430 = R_v2: ANOVO DESCRIPTION: RES;0 ,1/16W ,5% ,0402 ,SMT; ANOVO PART NUMBER: 271040000301; DUMMY: Not stuff; Part Type: RESISTOR; SMT: YES
R455 R456 R667-R671 = R_v2: ANOVO DESCRIPTION: RES;10K ,1/16W ,5% ,0402 ,SMT; ANOVO PART NUMBER: 271040103301; BACKSIDE: 0; Part Type: RESISTOR; SMT: YES
R678-R680 = R_v2: ANOVO DESCRIPTION: RES;1M ,1/16W ,5% ,0402 ,SMT; ANOVO PART NUMBER: 271040105301; BACKSIDE: 0; Part Type: RESISTOR; SMT: YES
SW1 = SMD-SW-8PIN_1: W/O Socket 10/100M: 1600000084; W/O Socket Giga: 1600000084; W/Socket Giga: 1600000084
U15 U17 = ICL3243ECA: ANOVO DESCRIPTION: IC,ICL3243ECA,UART Driver, SSOP28; ANOVO PART NUMBER: 286303243001; Part Type: IC
C314 = CAP_NP: ANOVO DESCRIPTION: CAP,22U ,CR,16V ,+80-20%,0805,Y5V,SMT,TAIYO; ANOVO PART NUMBER: 272003226401; BACKSIDE: 0; Part Type: CCAP; SMT: YES
C358 C359 C365 C368 = CAP_NP: ANOVO DESCRIPTION: CAP;22P ,50V ,5% ,0402 ,NPO ,SMT; ANOVO PART NUMBER: 272045220101; BACKSIDE: 0; Part Type: CCAP; SMT: YES
C628 C629 = CAP_NP: ANOVO DESCRIPTION: CAP;1000P ,1KV ,10% ,1206 ,X7R ,SMT; ANOVO PART NUMBER: 272431028011; Part Type: CCAP
Q4 Q5 = BCP69T: ANOVO DESCRIPTION: TRANS;BCP69T1,P-MOS,1A,SOT223,ON; ANOVO PART NUMBER: 288200069001; BACKSIDE: 0; Part Type: TRANSISTOR; SMT: YES
R168 R216 R232 R234 R245 R247 R251 R262 = R_v2: ANOVO DESCRIPTION: RES;47 ,1/16W ,5%, 0402 ,SMT; ANOVO PART NUMBER: 271040470301; BACKSIDE: 0; Part Type: RESISTOR; SMT: YES
R233 R248-R250 R263 R269 = R_v2: ANOVO DESCRIPTION: RES;0 ,1/16W ,5% ,0402 ,SMT; ANOVO PART NUMBER: 271040000301; BACKCOMP: YES; BACKSIDE: YES; ID: 0; Part Type: RESISTOR; SMT: YES
R235-R242 R254-R261 = R_v2: ANOVO DESCRIPTION: RES;49.9 ,1/16W ,1% ,0402 ,SMT; ANOVO PART NUMBER: 271040499811; BACKSIDE: 0; Part Type: RESISTOR; SMT: YES
R244 R253 = R_v2: ANOVO DESCRIPTION: RES;100 ,1/16W ,1% ,0402 ,SMT; ANOVO PART NUMBER: 271040101101; Part Type: RESISTOR
R458-R473 = R_v2: ANOVO DESCRIPTION: RES;3.3K ,1/16W ,5% ,0402 ,SMT; ANOVO PART NUMBER: 271040332301; Part Type: RESISTOR
R610-R614 R616 R618-R621 = R_v2: ANOVO DESCRIPTION: RES;1K ,1/16W ,1% ,0402 ,SMT; ANOVO PART NUMBER: 271040102101; Part Type: RESISTOR
R615 R617 = R_v2: ANOVO DESCRIPTION: RES;4.99K ,1/16W ,1% ,0402 ,SMT; ANOVO PART NUMBER: 271040499111; POWER: 1/16W; Part Type: RESISTOR
R803 R804 = R_v2: ANOVO DESCRIPTION: RES;0 ,1/16W ,5% ,0402 ,SMT; ANOVO PART NUMBER: 271040000301; POWER: 1/16W; Part Type: RESISTOR
R805-R812 = R_v2: ANOVO DESCRIPTION: RES;75 ,1/16W ,1% ,0402 ,SMT; ANOVO PART NUMBER: 271040750101; POWER: 1/16W; Part Type: RESISTOR
T1 = C33F22: ANOVO DESCRIPTION: TRANSFORMER,1000M/100M,30F-22,YDS; ANOVO PART NUMBER: 287303022001; BACKSIDE: 0; Part Type: TRANSFORMER; SMT: YES
U32 U35 = 283476530001: ANOVO DESCRIPTION: IC;EEPROM,AT25010AN-10SU-2.7,128*8,2.7V-5.5V,I2C,SOIC,8P,M6010; ANOVO PART NUMBER: 283402501001
U72 U73 = 284582573017_1: ANOVO DESCRIPTION: IC;PC82573L,GIGABIT ETHERNET CTLR,REV:SL8JD,BGA,196P; ANOVO PART NUMBER: 286308257302
Y8 Y9 = CRYSTAL: JM5; 8ND PART FIELD: BOT; ANOVO DESCRIPTION: Xtal;25MHz,+-30ppm,20pF,5032,2P,SMT; ANOVO PART NUMBER: 274022505400; Function Code: LAN; Part Description: XTAL SMD 25MHZ(+-30PPM5*3.2)7A25000058LF; Part Number: BG625000737; PartType: Crystal; Subsystem ID: LOM
T2 = C33F22: ANOVO DESCRIPTION: TRANSFORMER,1000M/100M,30F-22,YDS; ANOVO PART NUMBER: 287303022001; BACKSIDE: 0; OPTION: LAN1_540_541; Part Type: TRANSFORMER; SMT: YES
C377 C378 = CAP_NP: ANOVO DESCRIPTION: CAP;1U ,16V ,+80-20% ,0603 ,Y5V ,SMT; ANOVO PART NUMBER: 272073105401
C380 C425 = CAP_NP: ANOVO DESCRIPTION: CAP;3.3P ,50V ,+-0.25PF ,5%,0402 ,NPO ,SMT; ANOVO PART NUMBER: 272045033101
L13 L14 = FERRITE_BEAD: ANOVO DESCRIPTION: FERRITE CHIP;SMT;70 OHM/100MHZ;300MA;0805;CHILSIN; ANOVO PART NUMBER: 273007001300
R294 = R_v2: ANOVO DESCRIPTION: RES;8.2K ,1/16W ,5% ,0402 ,SMT; ANOVO PART NUMBER: 271040822301; BACKSIDE: 0; DUMMY: Not stuff; Part Type: RESISTOR; SMT: YES
R309 = R_v2: ANOVO DESCRIPTION: RES;10K ,1/16W ,5% ,0402 ,SMT; ANOVO PART NUMBER: 271040103301; BACKSIDE: 0; DUMMY: Not stuff; Part Type: RESISTOR; SMT: YES
R312 R319 R329 = R_v2: ANOVO DESCRIPTION: RES;4.7K ,1/16W ,5% ,0402 ,SMT; ANOVO PART NUMBER: 271040472301
R314 R321 R323-R325 R350-R352 R367 R379 = R_v2: ANOVO DESCRIPTION: RES;10K ,1/16W ,5% ,0402 ,SMT; ANOVO PART NUMBER: 271040103301
R316 = R_v2: ANOVO DESCRIPTION: RES;8.2K ,1/16W ,5% ,0402 ,SMT; ANOVO PART NUMBER: 271040822301
R327 R353 R371 = R_v2: ANOVO DESCRIPTION: RES;10K ,1/16W ,5% ,0402 ,SMT; ANOVO PART NUMBER: 271040103301; DUMMY: Not stuff
R363 = R_v2: ANOVO DESCRIPTION: RES;33K £¬1/16W £¬5% £¬0402 £¬SMT; ANOVO PART NUMBER: 271040333301; DUMMY: Not stuff
R366 R381 = R_v2: ANOVO DESCRIPTION: RES;6.8K £¬1/10W £¬5% £¬0603 £¬SMT; ANOVO PART NUMBER: 271071682301
R368 R369 = R_v2: ANOVO DESCRIPTION: RES;0 ,1/16W ,5% ,0402 ,SMT; ANOVO PART NUMBER: 271040000301
R370 = R_v2: ANOVO DESCRIPTION: RES;10M £¬1/10W £¬5% £¬0603 £¬SMT; ANOVO PART NUMBER: 271071106301
R383 = R_v2: ANOVO DESCRIPTION: RES;33K £¬1/16W £¬5% £¬0402 £¬SMT; ANOVO PART NUMBER: 271040333301
R392 = R_v2: ANOVO DESCRIPTION: RES;0 ,1/16W ,5% ,0402 ,SMT; ANOVO PART NUMBER: 271040000301; DUMMY: Not stuff
R560 = R_v2: ANOVO DESCRIPTION: RES;0 ,1/10W ,5% ,0603 ,SMT; ANOVO PART NUMBER: 271071000301; DUMMY: Not stuff
R639 = R_THERMISTOR: ANOVO DESCRIPTION: THERMISTOR,10K,NTC,3%,0603,SMT; ANOVO PART NUMBER: 310111103001; BACKSIDE: 0; Part Type: THERMISTOR; ROOM: SUPIO; SMT: YES
U16 = IT8712H_AP_48: IC;IT8781F-FX-L,SIO,QFP-128P,ITE; Anovo Part Number: 286308781001

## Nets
+1.8VSUS: R351.2 ; also on sheet 9 11 12 14 32 33 38 39
+1.25V: R324.2 ; also on sheet 9 12 18 32
+3V: C406.1 C407.1 R294.1 R321.2 R325.2 R326.2 R328.2 R610.2 R611.2 R613.2 R616.2 R618.2 R619.2 R667.2 R668.2 R669.2 R670.2 R680.2 U13.1(DVDD1) U13.9(DVDD2) ; also on sheet 4 9 10 12 15 16 17 18 24 25 26 27 28 31 32 34 35 41
+3V_DUAL: C309.1 C310.1 C314.1 C316.1 C321.1 C324.1 C327.1 C328.1 C329.1 C330.1 C508.2 C510.2 C523.1 C554.2 Q4.3(E) Q5.3(E) R248.1 R249.1 R309.2 R316.1 R319.2 R458.2 R459.2 R465.2 R466.2 R472.2 R473.2 R614.2 R621.2 U32.8(VCC) U35.8(VCC) U72.A2(IREG25_1) U72.A3(IREG25_2) U72.A7(VCC33_1) U72.D9(VCC33_2) U72.F3(VCC33_3) U72.J4(VCC33_4) U72.M10(VCC33_5) U72.N6(VCC33_6) U72.N8(VCC33_7) U72.P2(VCC33_8) U72.P12(VCC33_9) U73.A2(IREG25_1) U73.A3(IREG25_2) U73.A7(VCC33_1) U73.D9(VCC33_2) U73.F3(VCC33_3) U73.J4(VCC33_4) U73.M10(VCC33_5) U73.N6(VCC33_6) U73.N8(VCC33_7) U73.P2(VCC33_8) U73.P12(VCC33_9) ; also on sheet 14 15 16 17 18 26 31 33 34 38 40 41
+5V: C377.1 C430.1 C600.1 FB16.1 L13.2 R329.2 R336.2 R337.2 R338.2 R339.2 R348.2 R366.2 R367.1 R403.2 R671.2 U15.22(FORCEOFF#) U15.23(FORCEON) U15.26(VCC) U16.4(VCC) U16.35(VCC) U17.22(FORCEOFF#) U17.23(FORCEON) U17.26(VCC) ; also on sheet 18 24 25 26 27 29 30 31 32 33 34 35 40
+5V_ADO: C408.1 C409.2 C410.1 C411.1 FB16.2 U13.25(AVDD1) U13.38(AVDD2)
+5V_DUAL: C381.2 C424.1 R312.2 R314.1 R381.2 U16.67(VCCH) ; also on sheet 18 25 27 30 31 33 34
+12V_CPCI: R383.1 ; also on sheet 24 25 26 27 32 34
+VCCP: R352.2 ; also on sheet 5 6 7 10 11 12 15 18 31 32
AVDD25_LAN: C315.1 C317.1 C322.1 C323.1 C325.1 C479.2 C521.1 C555.1 C556.1 C557.1 C558.1 Q4.2(C2) Q4.4(C1) T1.1(TCT3) T1.4(TCT2) T1.7(TC1) T1.10(TCT0) T2.1(TCT3) T2.4(TCT2) T2.7(TC1) T2.10(TCT0) U72.A11(VCC25_1) U72.B1(VCC25_OUT1) U72.B2(VCC25_OUT2) U72.B6(VCC25_2) U72.G3(VCC25_3) U72.G5(VCC25_4) U72.H4(VCC25_5) U72.H5(VCC25_6) U72.J5(VCC25_7) U72.J12(VCC25_8) U72.K13(VCC25_9) U72.L12(VCC25_10) U72.M2(FUSEV) U72.M4(VCC25_11) U72.N7(VCC25_12) U73.A11(VCC25_1) U73.B1(VCC25_OUT1) U73.B2(VCC25_OUT2) U73.B6(VCC25_2) U73.G3(VCC25_3) U73.G5(VCC25_4) U73.H4(VCC25_5) U73.H5(VCC25_6) U73.J5(VCC25_7) U73.J12(VCC25_8) U73.K13(VCC25_9) U73.L12(VCC25_10) U73.M2(FUSEV) U73.M4(VCC25_11) U73.N7(VCC25_12)
GND: C250.1 C309.2 C310.2 C311.2 C312.2 C313.2 C314.2 C315.2 C316.2 C317.2 C318.2 C319.2 C320.2 C321.2 C322.2 C323.2 C324.2 C325.2 C326.2 C327.2 C328.2 C329.2 C330.2 C331.2 C332.2 C333.2 C334.2 C335.2 C336.2 C337.1 C338.2 C341.2 C358.1 C359.1 C365.1 C367.2 C368.1 C375.2 C377.2 C381.1 C406.2 C407.2 C423.2 C424.2 C428.1 C429.1 C430.2 C479.1 C508.1 C510.1 C512.1 C521.2 C522.2 C523.2 C524.2 C525.1 C554.1 C555.2 C556.2 C557.2 C558.2 C597.1 C599.1 C600.2 C628.1 C629.1 L14.2 Q34.2(SOURCE) R298.1 R327.1 R335.1 R350.1 R353.1 R355.1 R357.1 R455.1 R456.1 R460.1 R461.1 R462.1 R463.1 R464.2 R467.2 R468.1 R469.1 R470.1 R471.1 R612.2 R615.2 R617.2 R620.2 R678.1 R679.1 U13.4(DVSS1) U13.7(DVSS2) U15.25(GND) U16.15(GNDD) U16.50(GNDD) U16.74(GNDD) U16.117(GNDD) U17.25(GND) U32.4(GND) U35.4(GND) U72.A1(VSS1) U72.B3(VSS2) U72.C2(VSS3) U72.C10(VSS4) U72.C12(VSS5) U72.D2(VSS6) U72.D4(VSS7) U72.D5(VSS8) U72.D6(VSS9) U72.D7(VSS10) U72.D8(VSS11) U72.D13(VSS12) U72.E2(VSS13) U72.E4(VSS14) U72.E5(VSS15) U72.E6(VSS16) U72.E7(VSS17) U72.E8(VSS18) U72.E9(VSS19) U72.E10(VSS20) U72.F4(VSS21) U72.F5(VSS22) U72.F6(VSS23) U72.F7(VSS24) U72.F8(VSS25) U72.F9(VSS26) U72.F10(VSS27) U72.F11(VSS28) U72.G4(VSS29) U72.G7(VSS30) U72.G8(VSS31) U72.G9(VSS32) U72.G10(VSS33) U72.G11(VSS34) U72.G14(VSS35) U72.H9(VSS36) U72.H10(VSS37) U72.K2(VSS38) U72.N1(VSS39) U72.N12(VSS40) U72.P8(VSS41) U73.A1(VSS1) U73.B3(VSS2) U73.C2(VSS3) U73.C10(VSS4) U73.C12(VSS5) U73.D2(VSS6) U73.D4(VSS7) U73.D5(VSS8) U73.D6(VSS9) U73.D7(VSS10) U73.D8(VSS11) U73.D13(VSS12) U73.E2(VSS13) U73.E4(VSS14) U73.E5(VSS15) U73.E6(VSS16) U73.E7(VSS17) U73.E8(VSS18) U73.E9(VSS19) U73.E10(VSS20) U73.F4(VSS21) U73.F5(VSS22) U73.F6(VSS23) U73.F7(VSS24) U73.F8(VSS25) U73.F9(VSS26) U73.F10(VSS27) U73.F11(VSS28) U73.G4(VSS29) U73.G7(VSS30) U73.G8(VSS31) U73.G9(VSS32) U73.G10(VSS33) U73.G11(VSS34) U73.G14(VSS35) U73.H9(VSS36) U73.H10(VSS37) U73.K2(VSS38) U73.N1(VSS39) U73.N12(VSS40) U73.P8(VSS41) ; also on sheet 4 5 6 7 9 10 11 12 13 14 15 16 17 18 24 25 26 27 28 29 30 31 32 33 34 35 36 37 38 39 40 41
GND_TEMP: C378.2 C380.2 C422.1 C425.2 L14.1 R371.2 R639.1 U16.86(GNDA(D-)) ; also on sheet 5
VCC_CORE: R323.2 ; also on sheet 6 31 32
VCCRTC: C250.2 C423.1 R370.2 U16.69(VBAT) ; also on sheet 15 18
VDD12_LAN: C311.1 C312.1 C313.1 C318.1 C319.1 C320.1 C337.2 C338.1 C367.1 C375.1 C512.2 C524.1 C525.2 Q5.2(C2) Q5.4(C1) U72.A10(VCC12_1) U72.C4(VCC12_3) U72.C5(VCC12_2) U72.F12(VCC12_4) U72.G6(VCC12_5) U72.G12(VCC12_6) U72.G13(VCC12_7) U72.H6(VCC12_8) U72.H7(VCC12_9) U72.H8(VCC12_10) U72.H11(VCC12_11) U72.H12(VCC12_12) U72.J6(VCC12_13) U72.J7(VCC12_14) U72.J8(VCC12_15) U72.J9(VCC12_16) U72.J10(VCC12_17) U72.J11(VCC12_18) U72.K3(VCC12_19) U72.K4(VCC12_20) U72.K5(VCC12_21) U72.K6(VCC12_22) U72.K7(VCC12_23) U72.K8(VCC12_24) U72.K9(VCC12_25) U72.K10(VCC12_26) U72.K11(VCC12_27) U72.L5(VCC12_28) U72.L9(VCC12_29) U72.L10(VCC12_30) U73.A10(VCC12_1) U73.C4(VCC12_3) U73.C5(VCC12_2) U73.F12(VCC12_4) U73.G6(VCC12_5) U73.G12(VCC12_6) U73.G13(VCC12_7) U73.H6(VCC12_8) U73.H7(VCC12_9) U73.H8(VCC12_10) U73.H11(VCC12_11) U73.H12(VCC12_12) U73.J6(VCC12_13) U73.J7(VCC12_14) U73.J8(VCC12_15) U73.J9(VCC12_16) U73.J10(VCC12_17) U73.J11(VCC12_18) U73.K3(VCC12_19) U73.K4(VCC12_20) U73.K5(VCC12_21) U73.K6(VCC12_22) U73.K7(VCC12_23) U73.K8(VCC12_24) U73.K9(VCC12_25) U73.K10(VCC12_26) U73.K11(VCC12_27) U73.L5(VCC12_28) U73.L9(VCC12_29) U73.L10(VCC12_30)
VIN0: R323.1 U16.98(VIN0)
VIN1: R324.1 U16.97(VIN1)
VIN2: R325.1 U16.96(VIN2)
VIN3: R327.2 R366.1 U16.95(VIN3/ATXPG)
VIN4: R350.2 R383.2 U16.94(VIN4)
VIN5: R351.1 U16.93(VIN5)
VIN6: R352.1 U16.92(VIN6)
VIN7: R353.2 R381.1 U16.91(VIN7)
ACZ_RST#_AUDIO: U13.11(RESET#) ; also on sheet 15
ACZ_SDIN0: R297.2 ; also on sheet 15
ACZ_SDOUT_AUDIO: U13.5(SDATA-OUT) ; also on sheet 15
ACZ_SPKR: R386.2 ; also on sheet 17 25
ACZ_SYNC_AUDIO: U13.10(SYNC) ; also on sheet 15
ADOGND: C396.1 C404.2 C408.2 C409.1 C410.2 C411.2 R288.1 R298.2 R310.1 R322.2 R335.2 U13.26(AVSS1) U13.42(AVSS2) ; also on sheet 29
AUDIO_OUTL: FB13.2 ; also on sheet 29
AUDIO_OUTR: FB12.2 ; also on sheet 29
BIT_CLK_AUDIO: R299.2 ; also on sheet 15
CDIN_GND: C481.2 R310.2
CDIN_L: C482.2
CDIN_R: C480.2
CLK_PCIE_LAN1: U72.G1(PE_CLKP) ; also on sheet 4
CLK_PCIE_LAN1#: U72.G2(PE_CLKN) ; also on sheet 4
CLK_PCIE_LAN2: U73.G1(PE_CLKP) ; also on sheet 4
CLK_PCIE_LAN2#: U73.G2(PE_CLKN) ; also on sheet 4
CLKLPC2_48: U16.49(CLKIN) ; also on sheet 4
CODEC-BITCLK: R299.1 U13.6(BIT-CLK)
CODEC_SDIN0: R297.1 U13.8(SDATA-IN)
COM1_MODE: R679.2 SW1.1 ; also on sheet 24
COM1_RX: R338.1 U16.124(SOUT1/JP3) ; also on sheet 24
COM1_TX: U16.125(SIN1) ; also on sheet 24
COM2_CTS-: U16.128(CTS2#) ; also on sheet 24
COM2_DCD-: U16.126(DCD2#) ; also on sheet 24
COM2_DSR-: U16.3(DSR2#) ; also on sheet 24
COM2_DTR-: R348.1 U16.1(DTR2#/JP4) ; also on sheet 24
COM2_MODE: R678.2 SW1.2 ; also on sheet 24
COM2_RI-: U16.127(RI2#) ; also on sheet 24
COM2_RTS-: R403.1 U16.2(RTS2#/JP5) ; also on sheet 24
COM3_CTS#: R424.1 U17.4(R1IN) ; also on sheet 40
COM3_DCD#: R430.1 U17.8(R5IN) ; also on sheet 40
COM3_DSR#: R427.1 U17.5(R2IN) ; also on sheet 40
COM3_DTR#: R423.1 U17.11(T3OUT) ; also on sheet 40
COM3_RI#: R429.1 U17.7(R4IN) ; also on sheet 40
COM3_RTS#: R422.1 U17.10(T2OUT) ; also on sheet 40
COM3_RX: R428.1 U17.6(R3IN) ; also on sheet 40
COM3_TX: R421.1 U17.9(T1OUT) ; also on sheet 40
COM4_CTS#: U15.4(R1IN) ; also on sheet 30
COM4_DCD#: U15.8(R5IN) ; also on sheet 30
COM4_DSR#: U15.5(R2IN) ; also on sheet 30
COM4_DTR#: U15.11(T3OUT) ; also on sheet 30
COM4_RI#: U15.7(R4IN) ; also on sheet 30
COM4_RTS#: U15.10(T2OUT) ; also on sheet 30
COM4_RX: U15.6(R3IN) ; also on sheet 30
COM4_TX: U15.9(T1OUT) ; also on sheet 30
CTS0-: U16.120(CTS1#) ; also on sheet 24
CTS#3: U16.16(CTS3#/GP33) U17.19(R1OUT)
CTS#4: U15.19(R1OUT) U16.24(CTS4#/GP23/SI)
DCD0-: U16.118(DCD1#) ; also on sheet 24
DCD#3: U16.13(DCD3#/GP35) U17.15(R5OUT)
DCD#4: U15.15(R5OUT) U16.22(DCD4#/GP25)
DSR0-: U16.123(DSR1#) ; also on sheet 24
DSR#3: U16.19(DSR3#/GP30) U17.18(R2OUT)
DSR#4: U15.18(R2OUT) U16.27(DSR4#/GP20)
DTR0-: R337.1 U16.121(DTR1#/JP1) ; also on sheet 24
DTR#3: U16.17(DTR3#/GP32) U17.12(T3IN)
DTR#4: U15.12(T3IN) U16.25(DTR4#GP22/SCK)
FRONT-L: ACE4.1 U13.35(FRONT-L)
FRONT-R: ACE3.1 U13.36(FRONT-R)
FRONT_VGA_IN: Q34.1(GATE) R671.1 ; also on sheet 40
GATEA20: U16.46(GA20/JP7) ; also on sheet 15
H_THERMDA: C380.1 R363.2 R371.1 U16.87(TMPIN3) ; also on sheet 5
HOLD-_LAN1: R459.1 U32.7(HOLD_N)
HOLD-_LAN2: R472.1 U35.7(HOLD_N)
IDE_MODE_SEL: R668.1 SW1.3 ; also on sheet 24
J5_COM3_DCD#: R430.2 ; also on sheet 30
J5_COM3_DSR#: R427.2 ; also on sheet 30
J5_COM3_DTR#: R423.2 ; also on sheet 30
J5_COM3_RI#: R429.2 ; also on sheet 30
J5_COM3_RTS#: R422.2 ; also on sheet 30
J5_COM3_RX: R428.2 ; also on sheet 30
J5_COM3_TX: R421.2 ; also on sheet 30
J5COM3_CTS#: R424.2 ; also on sheet 30
KBCLK: U16.81(KCLK/GP60) ; also on sheet 30
KBDATA: U16.80(KDAT/GP61) ; also on sheet 30
KEYLOCK#: R329.1 U16.84(GP10)
LAD0/FWH0: U16.41(LAD0) ; also on sheet 15 24
LAD1/FWH1: U16.42(LAD1) ; also on sheet 15 24
LAD2/FWH2: U16.43(LAD2) ; also on sheet 15 24
LAD3/FWH3: U16.44(LAD3) ; also on sheet 15 24
LAN1_ACT#: U72.C11(LED1#) ; also on sheet 28
LAN1_LNK_100#: U72.B11(LED0#) ; also on sheet 28
LAN1_LNK_1000#: U72.A12(LED2#) ; also on sheet 28
LAN1_P1V2_CTRL: Q5.1(B) R803.2 U72.P3(CTRL_12)
LAN1_P2V5_CTRL: Q4.1(B) R804.2 U72.A4(CTRL_25)
LAN1_TRD0N: T1.14(MXD0-) ; also on sheet 28
LAN1_TRD0P: T1.13(MXD0+) ; also on sheet 28
LAN1_TRD1N: T1.17(MX1-) ; also on sheet 28
LAN1_TRD1P: T1.16(MX1+) ; also on sheet 28
LAN1_TRD2N: T1.20(MX2-) ; also on sheet 28
LAN1_TRD2P: T1.19(MX2+) ; also on sheet 28
LAN1_TRD3N: T1.23(MX3-) ; also on sheet 28
LAN1_TRD3P: T1.22(MX3+) ; also on sheet 28
LAN1_TRD_0+: R235.2 T1.12(TD0+) U72.C13(MDIP[0])
LAN1_TRD_0-: R236.2 T1.11(TD0-) U72.C14(MDIN[0])
LAN1_TRD_1+: R237.2 T1.9(TD1+) U72.E13(MDIP[1])
LAN1_TRD_1-: R238.2 T1.8(TD1-) U72.E14(MDIN[1])
LAN1_TRD_2+: R239.2 T1.6(TD2+) U72.F13(MDIP[2])
LAN1_TRD_2-: R240.2 T1.5(TD2-) U72.F14(MDIN[2])
LAN1_TRD_3+: R241.2 T1.3(TD3+) U72.H13(MDIP[3])
LAN1_TRD_3-: R242.2 T1.2(TD3-) U72.H14(MDIN[3])
LAN2_ACT#: U73.C11(LED1#) ; also on sheet 28
LAN2_LNK_100#: U73.B11(LED0#) ; also on sheet 28
LAN2_LNK_1000#: U73.A12(LED2#) ; also on sheet 28
LAN2_P1V2_CTRL: R803.1 U73.P3(CTRL_12)
LAN2_P2V5_CTRL: R804.1 U73.A4(CTRL_25)
LAN2_TRD0N: T2.14(MXD0-) ; also on sheet 28
LAN2_TRD0P: T2.13(MXD0+) ; also on sheet 28
LAN2_TRD1N: T2.17(MX1-) ; also on sheet 28
LAN2_TRD1P: T2.16(MX1+) ; also on sheet 28
LAN2_TRD2N: T2.20(MX2-) ; also on sheet 28
LAN2_TRD2P: T2.19(MX2+) ; also on sheet 28
LAN2_TRD3N: T2.23(MX3-) ; also on sheet 28
LAN2_TRD3P: T2.22(MX3+) ; also on sheet 28
LAN2_TRD_0+: R254.2 T2.12(TD0+) U73.C13(MDIP[0])
LAN2_TRD_0-: R255.2 T2.11(TD0-) U73.C14(MDIN[0])
LAN2_TRD_1+: R256.2 T2.9(TD1+) U73.E13(MDIP[1])
LAN2_TRD_1-: R257.2 T2.8(TD1-) U73.E14(MDIN[1])
LAN2_TRD_2+: R258.2 T2.6(TD2+) U73.F13(MDIP[2])
LAN2_TRD_2-: R259.2 T2.5(TD2-) U73.F14(MDIN[2])
LAN2_TRD_3+: R260.2 T2.3(TD3+) U73.H13(MDIP[3])
LAN2_TRD_3-: R261.2 T2.2(TD3-) U73.H14(MDIN[3])
LDRQ#0: R326.1 U16.38(LDRQ#) ; also on sheet 15
LFRAME#/FWH4: U16.40(LFRAME#) ; also on sheet 15 24
LINE1-L: C392.1 U13.23(LINE1-L)
LINE1-R: C393.1 U13.24(LINE1-R)
LINE_L: FB10.2 ; also on sheet 29
LINE_R: FB11.2 ; also on sheet 29
MIC1-L: C401.1 U13.21(MIC1-L)
MIC1-R: C402.1 U13.22(MIC1-R)
MIC1-VREFO-L: R289.1 U13.28(MIC1-VREFO-L)
MIC1-VREFO-R: R290.1 U13.32(MIC1-VREFO-R)
MIC_IN: C404.1 FB14.2 R322.1 ; also on sheet 29
MIC_SYS: C401.2 C402.2 FB14.1 R289.2 R290.2
MSCLK: U16.83(MCLK/GP56) ; also on sheet 30
MSDATA: U16.82(MDAT/GP57) ; also on sheet 30
NVM1_CS-: R168.2 U32.1(CS_N)
NVM1_SI: R232.2 U32.5(SI)
NVM1_SK: R216.2 U32.6(SCK)
NVM1_SO: R234.2 U32.2(SO)
NVM2_CS-: R262.2 U35.1(CS_N)
NVM2_SI: R247.2 U35.5(SI)
NVM2_SK: R245.2 U35.6(SCK)
NVM2_SO: R251.2 U35.2(SO)
PACK#: U16.103(ACK#) ; also on sheet 26 28
PAFD#: U16.107(AFD#) ; also on sheet 26 28
PBUSY: U16.102(BUSY) ; also on sheet 26 28
PCI_PME#: R309.1 R432.2 ; also on sheet 16
PCIE_RXN0: C303.2 ; also on sheet 16
PCIE_RXN0_C: C303.1 U72.C1(PE_T0N)
PCIE_RXN1: C339.2 ; also on sheet 16
PCIE_RXP0: C304.2 ; also on sheet 16
PCIE_RXP0_C: C304.1 U72.D1(PE_T0P)
PCIE_RXP1: C340.2 ; also on sheet 16
PCIE_TXN0: U72.F1(PE_R0N) ; also on sheet 16
PCIE_TXN1: U73.F1(PE_R0N) ; also on sheet 16
PCIE_TXP0: U72.F2(PE_R0P) ; also on sheet 16
PCIE_TXP1: U73.F2(PE_R0P) ; also on sheet 16
PCIE_WAKE#: R263.1 R269.1 ; also on sheet 17 41
PCLK_LPC2: U16.47(PCICLK) ; also on sheet 4
PERROR#: U16.106(ERR#) ; also on sheet 26 28
PINIT#: U16.105(INIT#) ; also on sheet 26 28
PLTRST#: R233.1 R250.1 R369.1 ; also on sheet 16 24 35
PPD0: U16.109(PD0) ; also on sheet 26 28
PPD1: U16.110(PD1) ; also on sheet 26 28
PPD2: U16.111(PD2) ; also on sheet 26 28
PPD3: U16.112(PD3) ; also on sheet 26 28
PPD4: U16.113(PD4) ; also on sheet 26 28
PPD5: U16.114(PD5) ; also on sheet 26 28
PPD6: U16.115(PD6) ; also on sheet 26 28
PPD7: U16.116(PD7) ; also on sheet 26 28
PPE: U16.101(PE) ; also on sheet 26 28
PS_ON#: R575.2 ; also on sheet 30
PSLCT: U16.100(SLCT) ; also on sheet 26 28
PSLIN#: U16.104(SLIN#) ; also on sheet 26 28
PSTB#: U16.108(STB#) ; also on sheet 26 28
PWRBT_OUT#: R319.1 R577.1 U16.72(PWRON#/GP44)
PWRBTN: R576.2 ; also on sheet 17 25 30
PWROK: R392.1 ; also on sheet 9 17 26 31
PWROK_SIO2: R328.1 R392.2 U16.78(PWROK/GP41)
RCIN#: R321.1 U16.45(KRST#/GP62) ; also on sheet 15
RI0-: U16.119(RI1#) ; also on sheet 24
RI#3: U16.14(RI3#/GP34) U17.16(R4OUT)
RI#4: U15.16(R4OUT) U16.23(RI4#/GP24)
RS232_RX: R339.1 U16.5(SOUT2/JP6) ; also on sheet 24
RS232_TX: U16.6(SIN2) ; also on sheet 24
RSMRST#: R244.1 R253.1 R560.2 ; also on sheet 17 34 36 41
RSMRST#_SIO: R316.2 R560.1 U16.85(RSMRST#/GP55)
RTS0-: R336.1 U16.122(RTS1#/JP2) ; also on sheet 24
RTS#3: U16.18(RTS3#/GP31) U17.13(T2IN)
RTS#4: U15.13(T2IN) U16.26(RTS4#/GP21)
SERIRQ: R294.2 U16.39(SERIRQ) ; also on sheet 17
SIN3: U16.21(SIN3/GP26) U17.17(R3OUT)
SIN4: U15.17(R3OUT) U16.29(SIN4/GP16/SO)
SIO_PS_ON#: R314.2 R575.1 U16.76(PSON#/GP42)
SIO_PWRBTN: R312.1 R576.1 U16.75(PANSWH#/GP43)
SIOBTN: R577.2 ; also on sheet 17 36
SLP_S3#: R578.2 ; also on sheet 17 32 33 34
SLP_S5#: R368.1 ; also on sheet 17
SOUT3: U16.20(SOUT3/GP27) U17.14(T1IN)
SOUT4: U15.14(T1IN) U16.28(SOUT4/GP17/CE_N)
SYS_THERMDA: C425.1 R379.2 R639.2 U16.88(TMPIN2)
VGA_J_EN#: R436.1 R680.1 SW1.4 ; also on sheet 26
VREF (page 21--SIO ITE8781F 4 COM PORTS): C422.2 R363.1 R379.1 U16.90(VREF)
WP-_LAN1: R458.1 U32.3(WP_N)
WP-_LAN2: R473.1 U35.3(WP_N)
N18115860: C403.1 U13.12(PCBEEP)
N18115886: C403.2 C522.1 R357.2 R386.1
N18115896: C396.2 U13.27(VREF)
N18116015: R288.2 U13.40(JDREF/NC)
N53474296: ACE3.2 FB12.1
N53474338: ACE4.2 FB13.1
N57592556: R233.2 U72.P7(PE_RST#)
N57621679: C332.1 R258.1 R259.1
N57621681: C326.1 R254.1 R255.1
N57621683: C331.1 R256.1 R257.1
N57621685: C333.1 R260.1 R261.1
N76767315: C392.2 FB10.1
N76767317: C393.2 FB11.1
N99772739: R168.1 U72.B10(NVM_CS)
N99772977: R216.1 R455.2 U72.C9(NVM_SK)
N99776104: R232.1 U72.A9(NVM_SI)
N99779242: R234.1 U72.B9(NVM_SO)
N99846041: R460.2 U72.A5(NVM_PROT)
N99849162: R461.2 U72.A6(NVM_TYPE)
N99852285: R462.2 U72.D3(NVM_SHARED)
N99879799: R612.1 U72.N5(TCK)
N99879802: R610.1 U72.N4(TMS)
N99879805: R611.1 U72.P4(TDI)
N99921299: C365.2 U72.J14(XTAL2) Y8.2
N99921301: C358.2 U72.K14(XTAL1) Y8.1
N99955047: R613.1 U72.N11(SMB_ALRT)
N99965009: R614.1 U72.C6(AUX_PRESENT)
N99980783: R263.2 U72.P10(PE_WAKE#)
N99996760: R615.1 U72.D12(ISOL_TI/PHY_REF)
N100001799: R463.2 U72.A13(TEST_EN)
N100006137: C336.1 R239.1 R240.1
N100006139: C341.1 R241.1 R242.1
N100006145: C334.1 R235.1 R236.1
N100006147: C335.1 R237.1 R238.1
N100013719: R244.2 U72.P5(LAN_PWR_GOOD)
N100024644: R248.2 U72.L7(DEVICE_OFF#)
N100359358: R464.1 R465.1 U72.B5(EN25REG)
N100385214: R466.1 R467.1 U73.B5(EN25REG)
N100452488: R262.1 U73.B10(NVM_CS)
N100452498: R245.1 R456.2 U73.C9(NVM_SK)
N100452502: R269.2 U73.P10(PE_WAKE#)
N100452518: R616.1 U73.N11(SMB_ALRT)
N100452545: R470.2 U73.D3(NVM_SHARED)
N100452648: R247.1 U73.A9(NVM_SI)
N100452658: R620.1 U73.N5(TCK)
N100452660: R618.1 U73.N4(TMS)
N100452662: R619.1 U73.P4(TDI)
N100452682: R617.1 U73.D12(ISOL_TI/PHY_REF)
N100452695: R250.2 U73.P7(PE_RST#)
N100452725: R249.2 U73.L7(DEVICE_OFF#)
N100452749: C368.2 U73.J14(XTAL2) Y9.2
N100452751: C359.2 U73.K14(XTAL1) Y9.1
N100452795: R251.1 U73.B9(NVM_SO)
N100452831: R253.2 U73.P5(LAN_PWR_GOOD)
N100452843: R469.2 U73.A5(NVM_PROT)
N100452869: R471.2 U73.A13(TEST_EN)
N100452917: R621.1 U73.C6(AUX_PRESENT)
N100452990: R468.2 U73.A6(NVM_TYPE)
N100602442: C340.1 U73.D1(PE_T0P)
N100602450: C339.1 U73.C1(PE_T0N)
N100962443: R808.1 T1.24(MCT3)
N100968617: R807.1 T1.21(MCT2)
N100974795: R806.1 T1.18(MCT1)
N100980977: R805.1 T1.15(MCT0)
N100985479: C628.2 R805.2 R806.2 R807.2 R808.2
N101009485: R809.1 T2.15(MCT0)
N101009487: R811.1 T2.21(MCT2)
N101009541: C629.2 R809.2 R810.2 R811.2 R812.2
N101009573: R810.1 T2.18(MCT1)
N101009585: R812.1 T2.24(MCT3)
N103174036: C481.1 U13.19(CD-GND)
N103174037: C482.1 U13.18(CD-L)
N103174038: C480.1 U13.20(CD-R)
N110908882: C378.1 L13.1 U16.99(AVCC)
N110909341: R578.1 U16.71(SUSB#/GP45)
N110909575: R432.1 U16.73(PME#/GP54)
N110909747: R369.2 U16.37(LRESET#)
N110909763: R368.2 U16.77(SUSC#/GP53)
N110909856: R367.2 U16.30(RESETCON#/GP15)
N116072122: R669.1 SW1.5
N116072128: R667.1 SW1.7
N116370711: R355.2 SW1.6
N116606263: C549.2 U17.28(C1+)
N116606265: C549.1 U17.24(C1-)
N116606267: C551.1 U17.2(C2-)
N116606269: C551.2 U17.1(C2+)
N116606271: C597.2 U17.27(V+)
N116606273: C599.2 U17.3(V-)
N118914048: C426.2 U15.28(C1+)
N118914050: C426.1 U15.24(C1-)
N118914052: C427.1 U15.2(C2-)
N118914054: C427.2 U15.1(C2+)
N118914056: C428.2 U15.27(V+)
N118914058: C429.2 U15.3(V-)
N119424591: R670.1 SW1.8
N124501525: Q34.3(DRAIN) R436.2
N126027469: R370.1 U16.68(COPEN#)

Not connected (* = marked no-connect by the designer): U13 2(GPIO0)* 3(GPIO1)* 13(Sense_A)* 14(LINE2-L)* 15(LINE2-R)* 16(MIC2-L)* 17(MIC2-R)* 29(LINE1-VREFO-L)* 30(MIC2-VREFO)* 31(LINE2-VREFO)* 33(DCVOL)* 34(Sense_B)* 37(LINE1-VREFO-R)* 39(SURR-L)* 41(SURR-R)* 43(SURR-VREFO-L)* 44(SURR-VREFO-R)* 45(MIC2-VREFO-R)* 46(LINE2-VREFO-R)* 47(SPDIFI/EAPD)* 48(SPDIFO)*; U15 20(R2OUTB)* 21(INVALID#)*; U16 7(FAN_TAC1)* 8(FAN_CTL1)* 9(FAN_TAC2/GP52)* 10(FAN_CTL2/GP51)* 11(FAN_TAC3/GP37)* 12(FAN_CTL3/GP36)* 31(SCRRST/GP14)* 32(SCRPFET#/GP13)* 33(SCRIO/GP12)* 34(SCRCLK/GP11)* 36(Reserved)* 48(SCRPSNT#/GP50)* 51(DENSEL#)* 52(MTRA#)* 53(SST/MTRB#)* 54(DRVA#)* 55(PECI/DRVB#)* 56(WDATA#)* 57(DIR#)* 58(STEP#)* 59(HDSEL#)* 60(WGATE#)* 61(RDATA#)* 62(TRK0#)* 63(INDEX#)* 64(WPT#)* 65(DSKCHG#)* 66(IRTX/GP47)* 70(IRRX/GP46)* 79(3VSBSW#/GP40)* 89(TMPIN1)*; U17 20(R2OUTB)* 21(INVALID#)*; U72 A8(SDP0)* A14(TEST16)* B4(NVM_REQ)* B7(NC1)* B8(SDP1)* B12(PHY_HSDACP)* B13(PHY_HSDACN)* B14(PHY_TSTPT)* C3(DOCK_INO)* C7(SDP3)* C8(SDP2)* D10(ISOL_TEX)* D11(NC10)* D14(ISOL_TCK)* E1(NC6)* E3(TEST15)* E11(NC7)* E12(NC8)* H1(TEST0)* H2(TEST1)* H3(TEST2)* J1(TEST3)* J2(TEST4)* J3(TEST5)* J13(NC11)* K1(TEST6)* K12(NC2)* L1(TEST7)* L2(THERMn)* L3(THERMp)* L4(NC9)* L6(NC3)* L8(NC12)* L11(NC4)* L13(LAN_TXD1)* L14(LAN_TXD2)* M1(TEST8)* M3(TEST9)* M5(NC13)* M6(NC5)* M7(NC14)* M8(TEST13)* M9(NC15)* M11(SMB_DATA)* M12(LAN_RXD2)* M13(LAN_RSTAYNC)* M14(LAN_TXD0)* N2(TEST10)* N3(TEST12)* N9(NC16)* N10(PHY_CLK125)* N13(LAN_RXD1)* N14(LAN_CLK)* P1(TEST11)* P6(TDO)* P9(TEST14)* P11(SMB_CLK)* P13(LAN_RXD0)* P14(NC17)*; U73 A8(SDP0)* A14(TEST16)* B4(NVM_REQ)* B7(NC1)* B8(SDP1)* B12(PHY_HSDACP)* B13(PHY_HSDACN)* B14(PHY_TSTPT)* C3(DOCK_INO)* C7(SDP3)* C8(SDP2)* D10(ISOL_TEX)* D11(NC10)* D14(ISOL_TCK)* E1(NC6)* E3(TEST15)* E11(NC7)* E12(NC8)* H1(TEST0)* H2(TEST1)* H3(TEST2)* J1(TEST3)* J2(TEST4)* J3(TEST5)* J13(NC11)* K1(TEST6)* K12(NC2)* L1(TEST7)* L2(THERMn)* L3(THERMp)* L4(NC9)* L6(NC3)* L8(NC12)* L11(NC4)* L13(LAN_TXD1)* L14(LAN_TXD2)* M1(TEST8)* M3(TEST9)* M5(NC13)* M6(NC5)* M7(NC14)* M8(TEST13)* M9(NC15)* M11(SMB_DATA)* M12(LAN_RXD2)* M13(LAN_RSTAYNC)* M14(LAN_TXD0)* N2(TEST10)* N3(TEST12)* N9(NC16)* N10(PHY_CLK125)* N13(LAN_RXD1)* N14(LAN_CLK)* P1(TEST11)* P6(TDO)* P9(TEST14)* P11(SMB_CLK)* P13(LAN_RXD0)* P14(NC17)*

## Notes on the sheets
sheet 22
- SW1 Default value: OFF
- GigaLAN OUT SEL
- 4
- 4
- 4
- 4
- 3
- 3
- 3
- 3
- 2
- 2
- 2
- 2
- SW1
- ON
- 1
- SW1
- ON
- 1
- SW1
- ON
- 1
- SW1
- ON
- 1
- COM1
  OFF:RS232
  ON: RS422
- COM2
  OFF:RS232
  ON: RS422
- IDE MS/SL
  OFF: SLAVE
  ON:  MASTER
- VGA
  OFF: FRONT OUT
  ON:  REAR IO
